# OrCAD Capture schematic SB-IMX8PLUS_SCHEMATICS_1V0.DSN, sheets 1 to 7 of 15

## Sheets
1 01. Block Diagram: title: SB-iMX8PLUS   01. INDEX; rev: 1.0; note: 8000171000
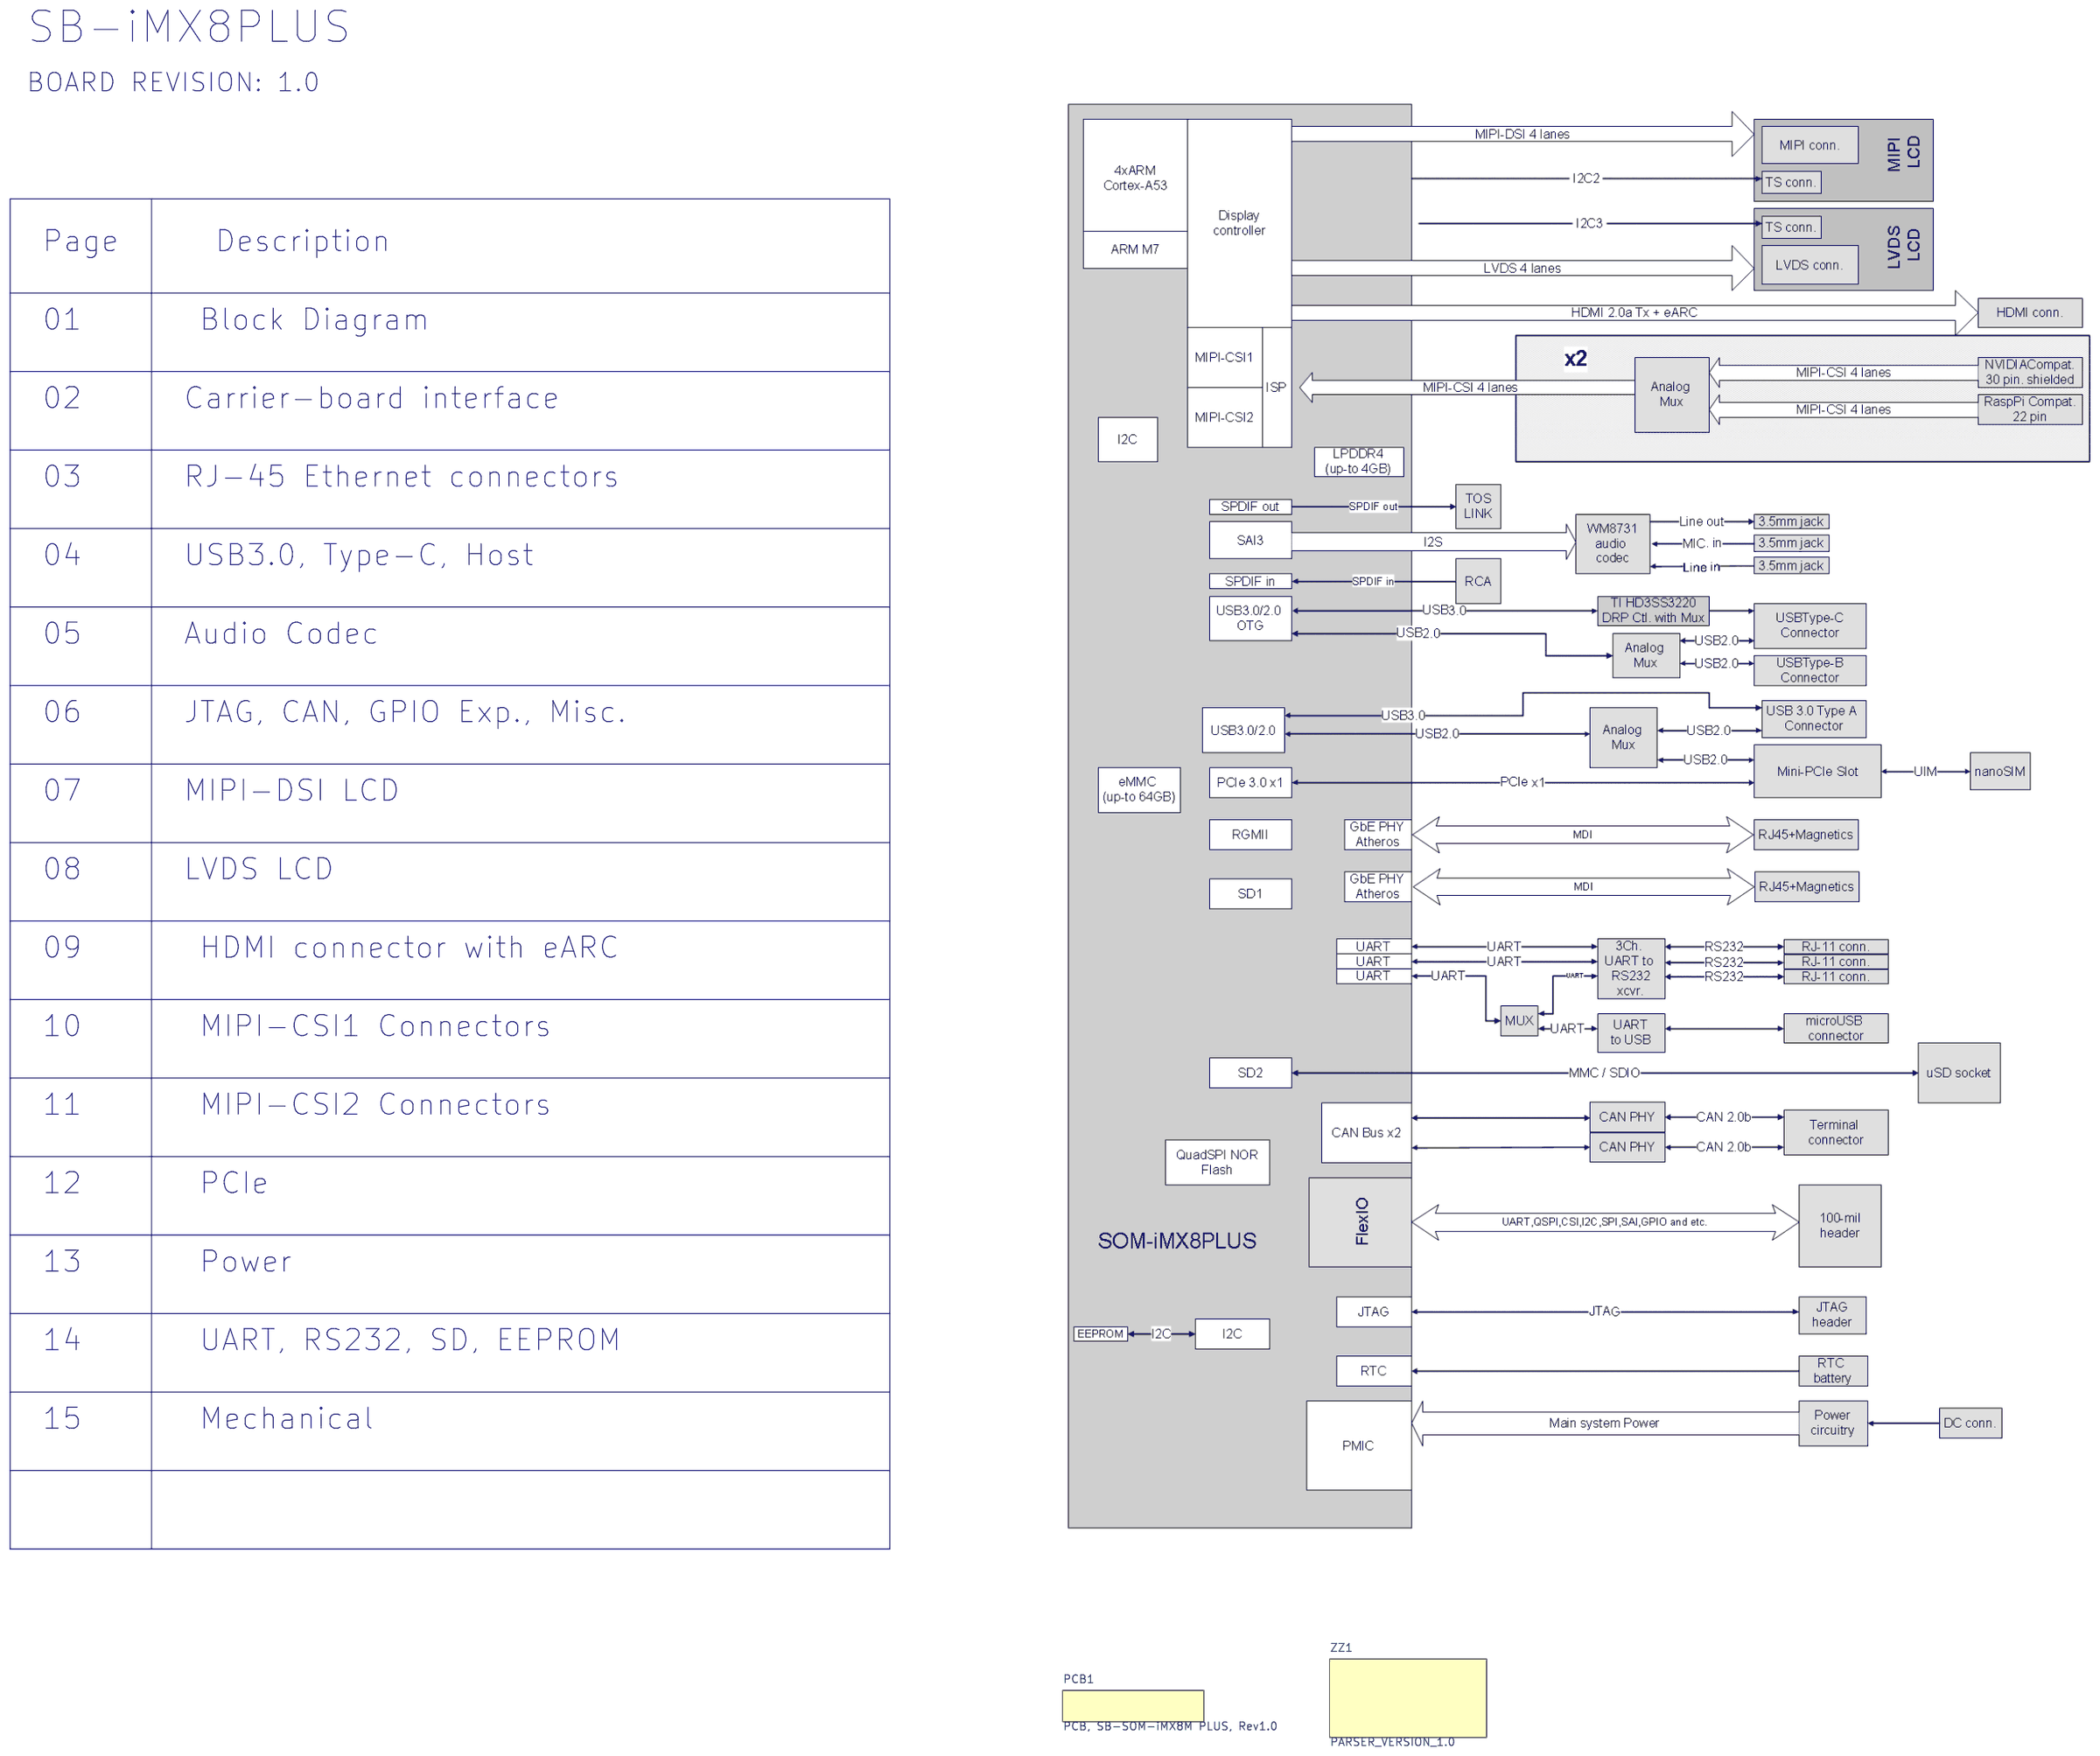
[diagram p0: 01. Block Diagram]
2 02. Carrier Board interface: size C; title: SB-iMX8 PLUS   02. CARRIER BOARD INTERFACE; rev: 1.3; note: 17 HaYetsira Street; note: Yokneam Illit, Israel 2069208
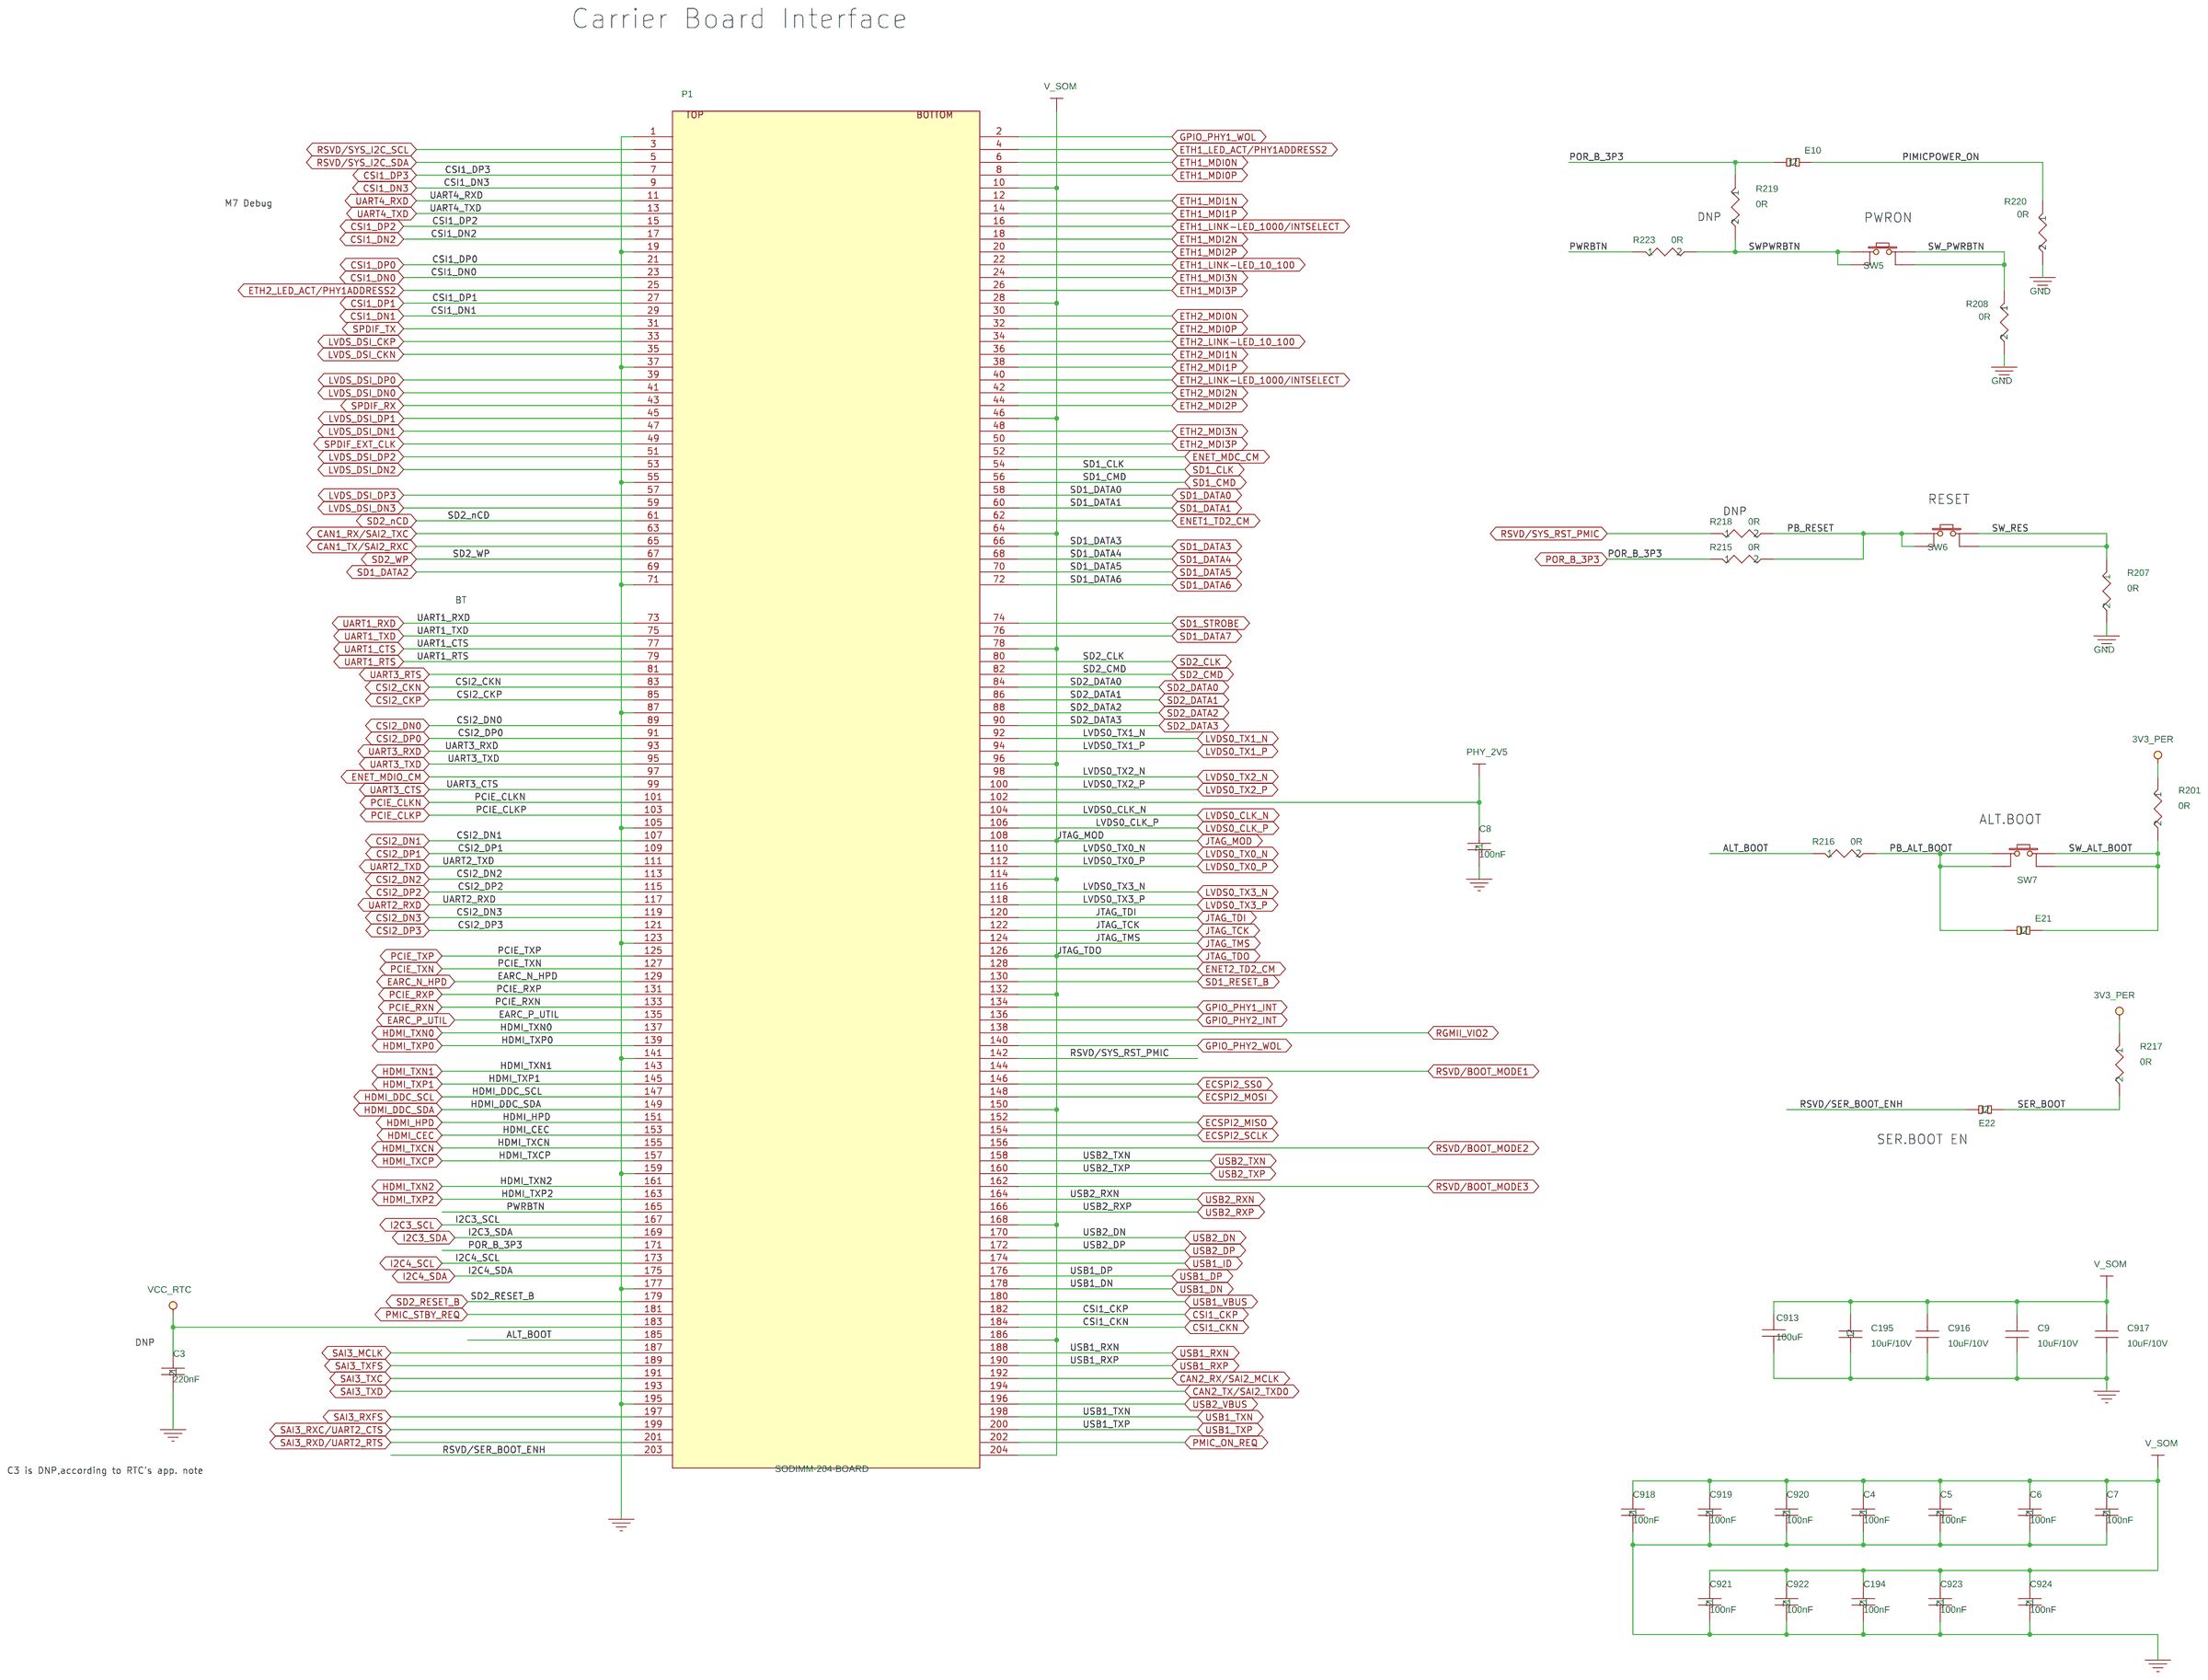
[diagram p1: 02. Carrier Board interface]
3 03. RJ-45 Ethernet connector: size A3; title: SB-iMX8PLUS      03. Gigabit Ethernet
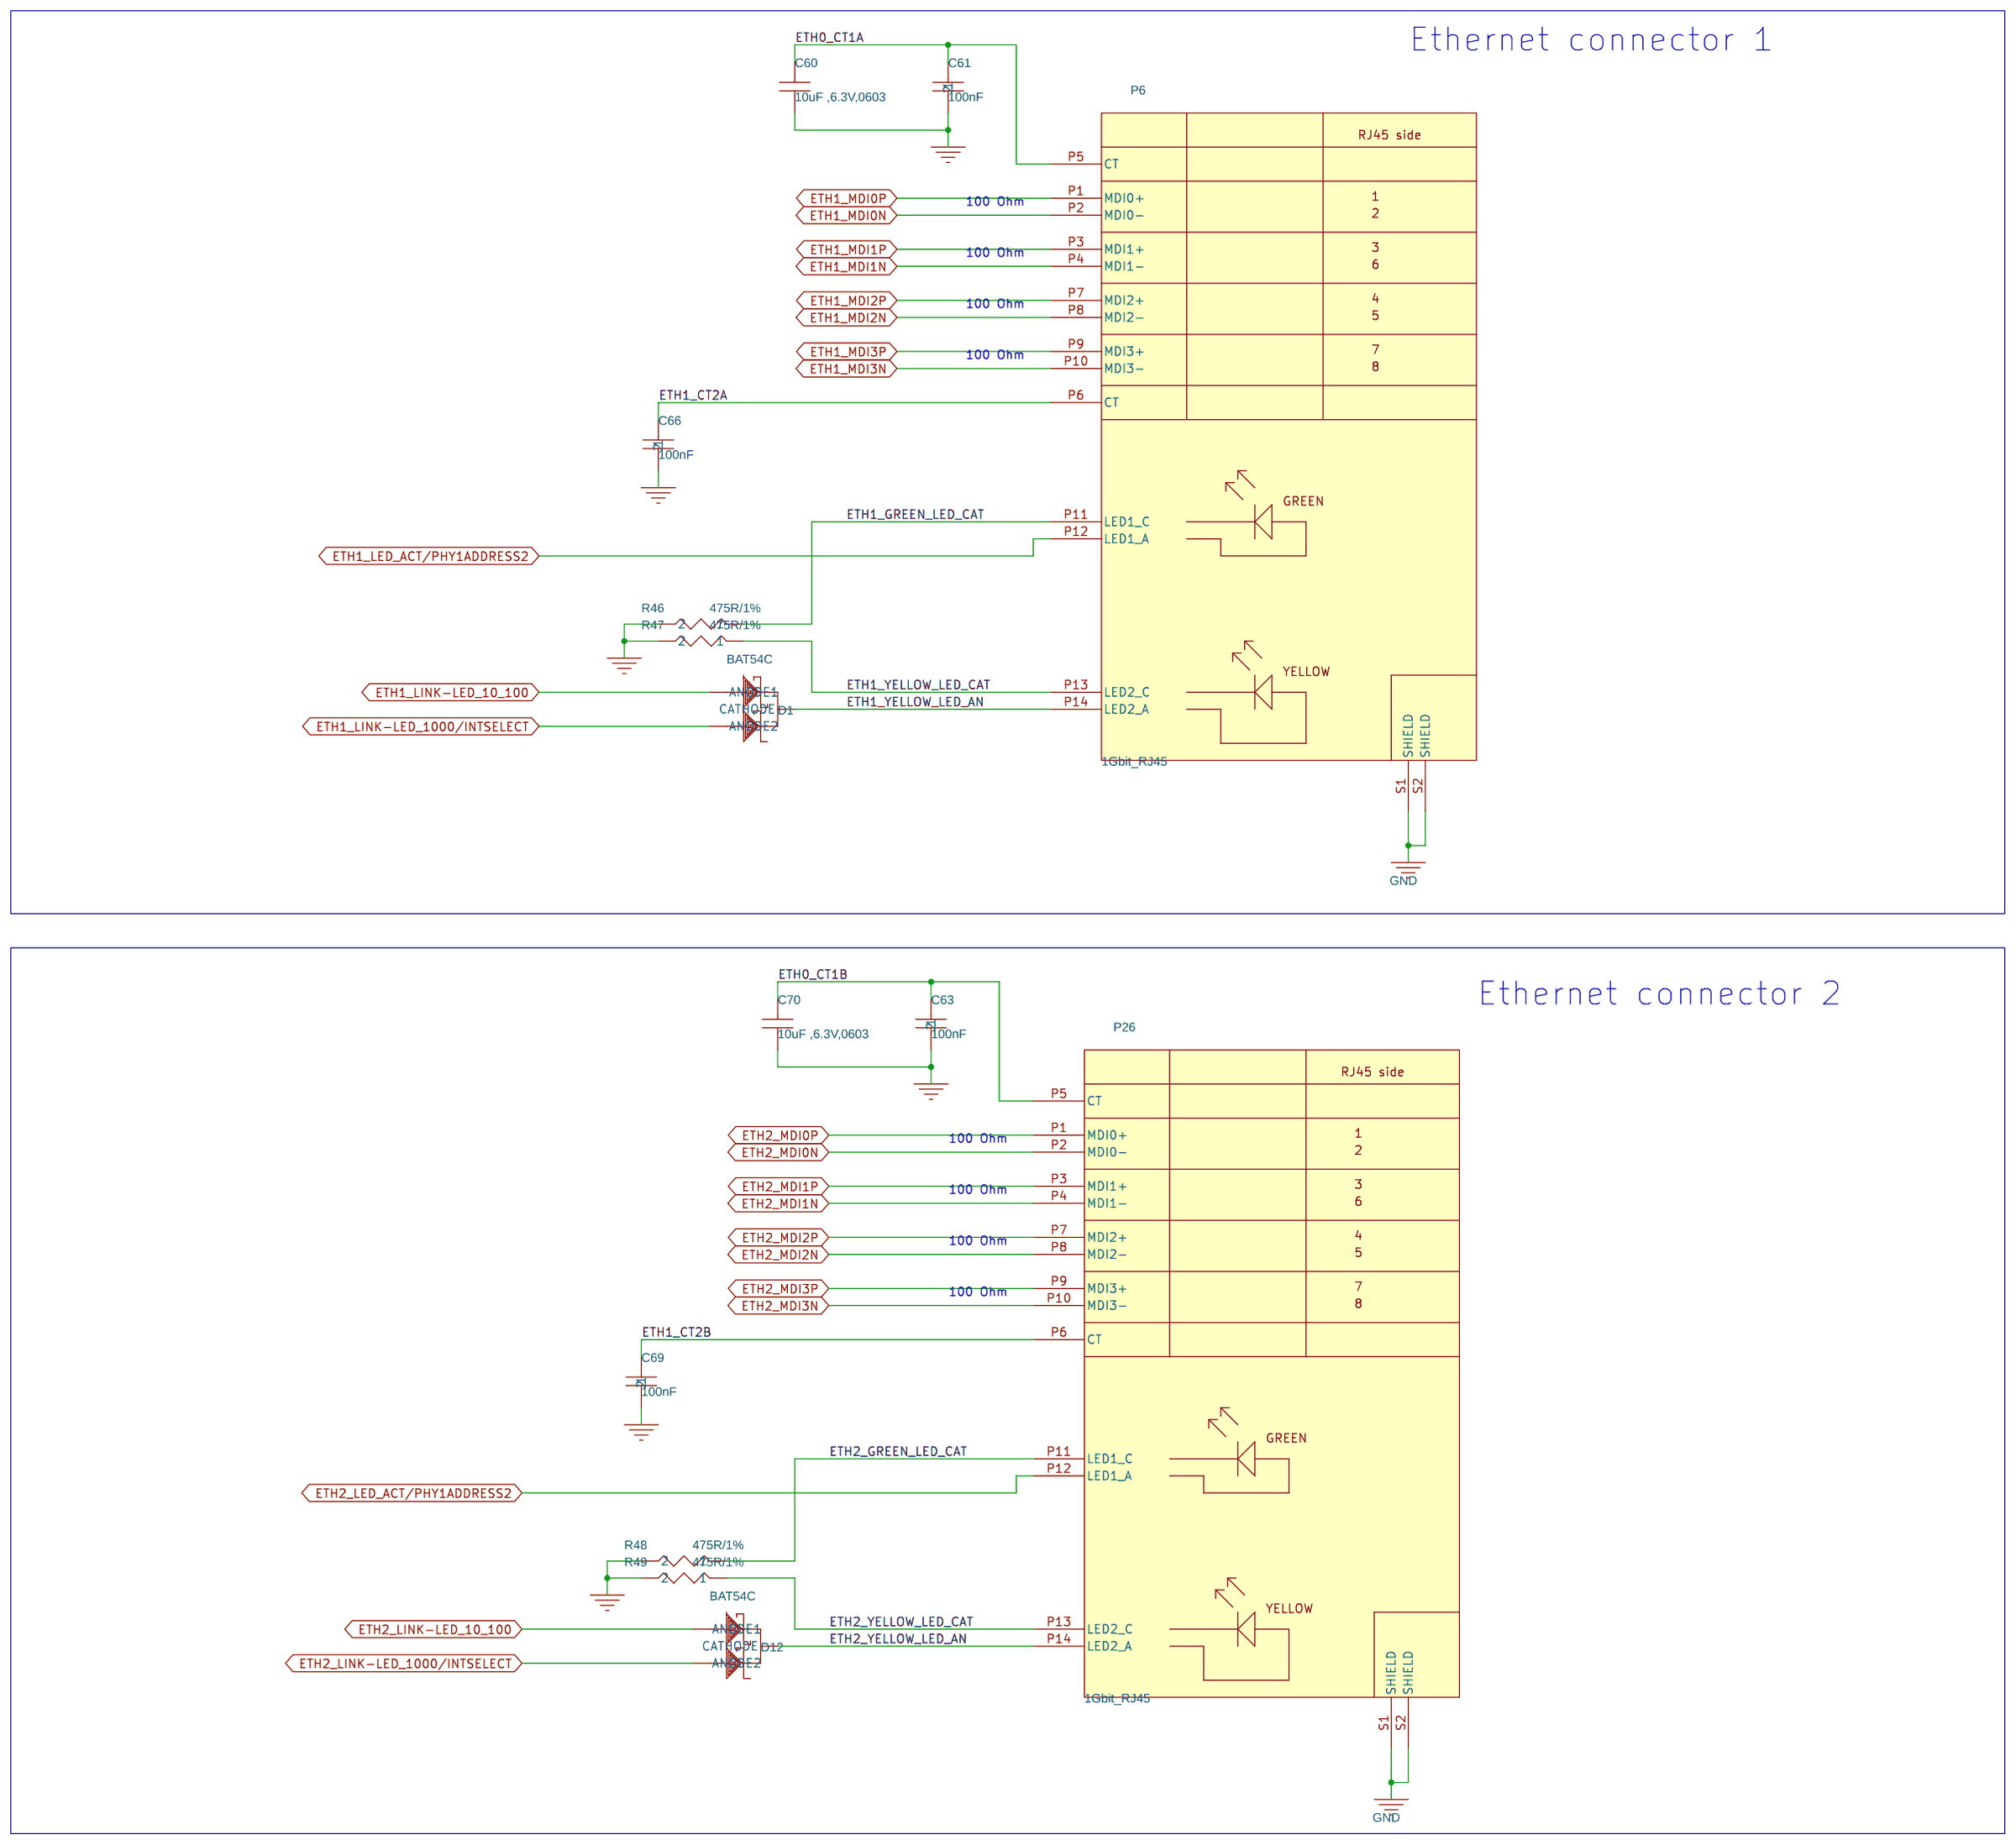
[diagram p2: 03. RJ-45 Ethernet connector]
4 04. USB3.0, Type-C, Host: size A3; title: SB-iMX8PLUS    04. USB3.0, Type-C, Host
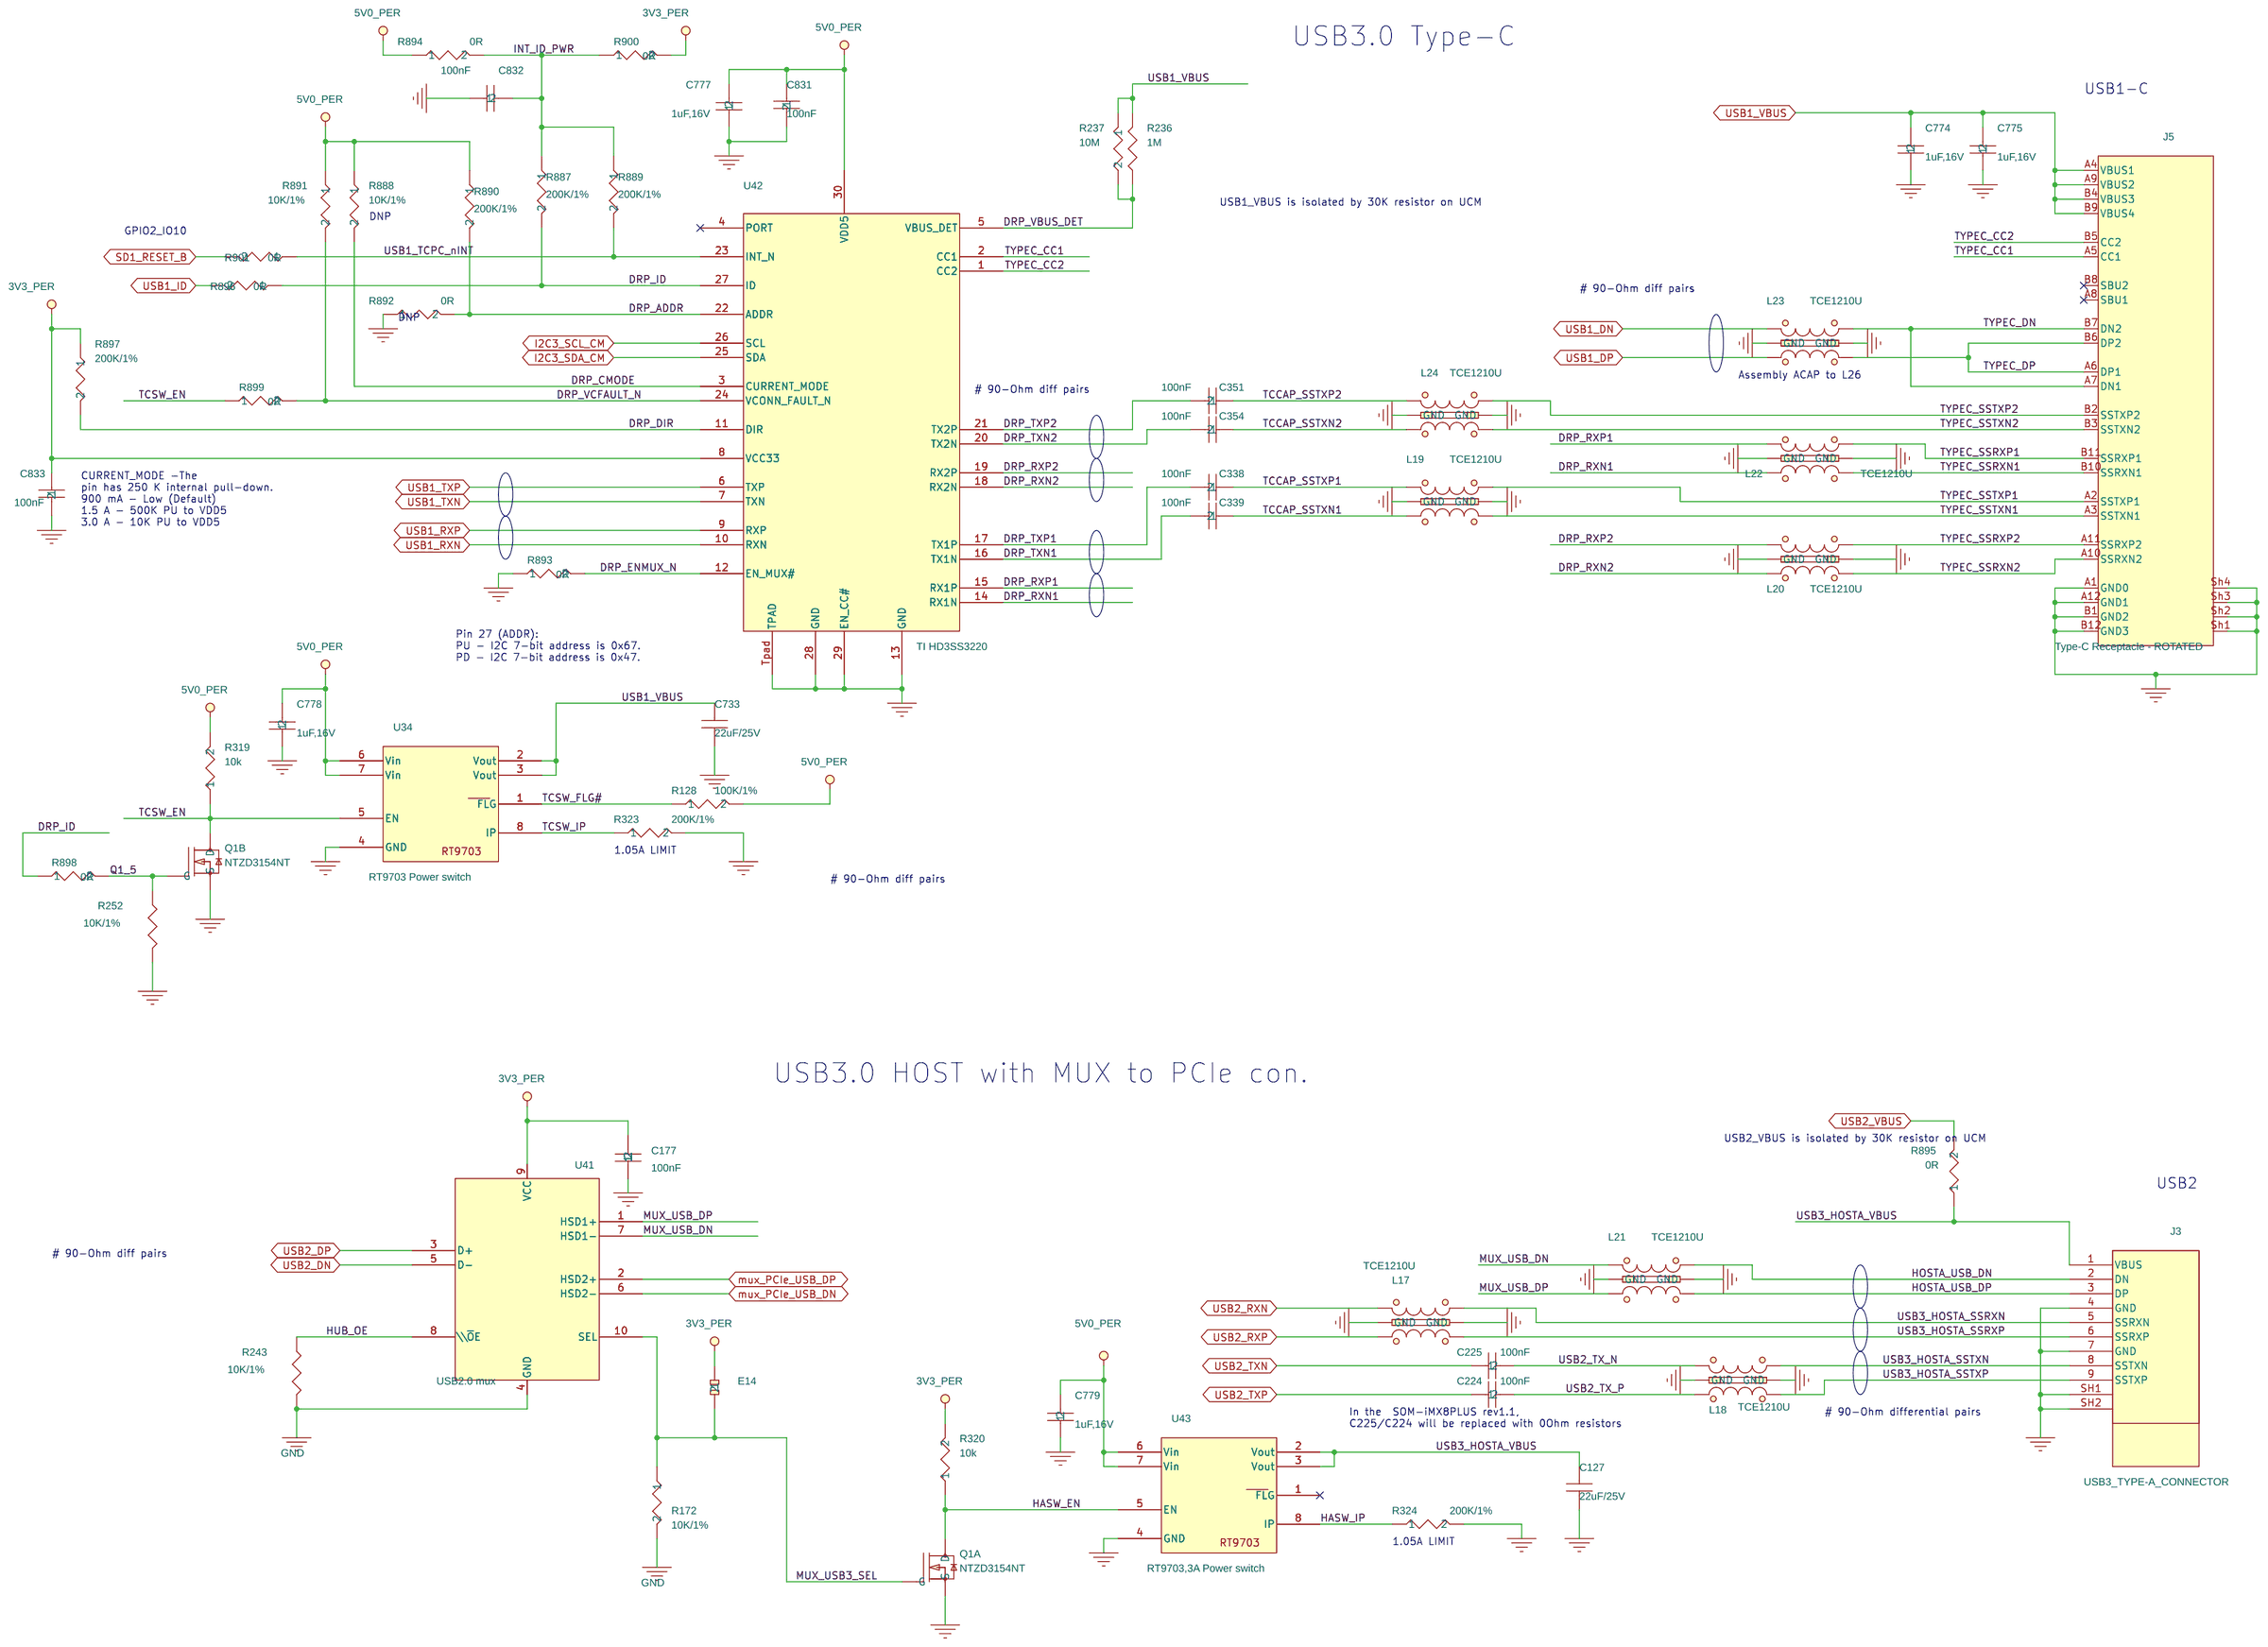
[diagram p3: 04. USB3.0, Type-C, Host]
5 05. Audio Codec: size A3; title: SB-iMX8PLUS      05. AUDIO,SPDIF
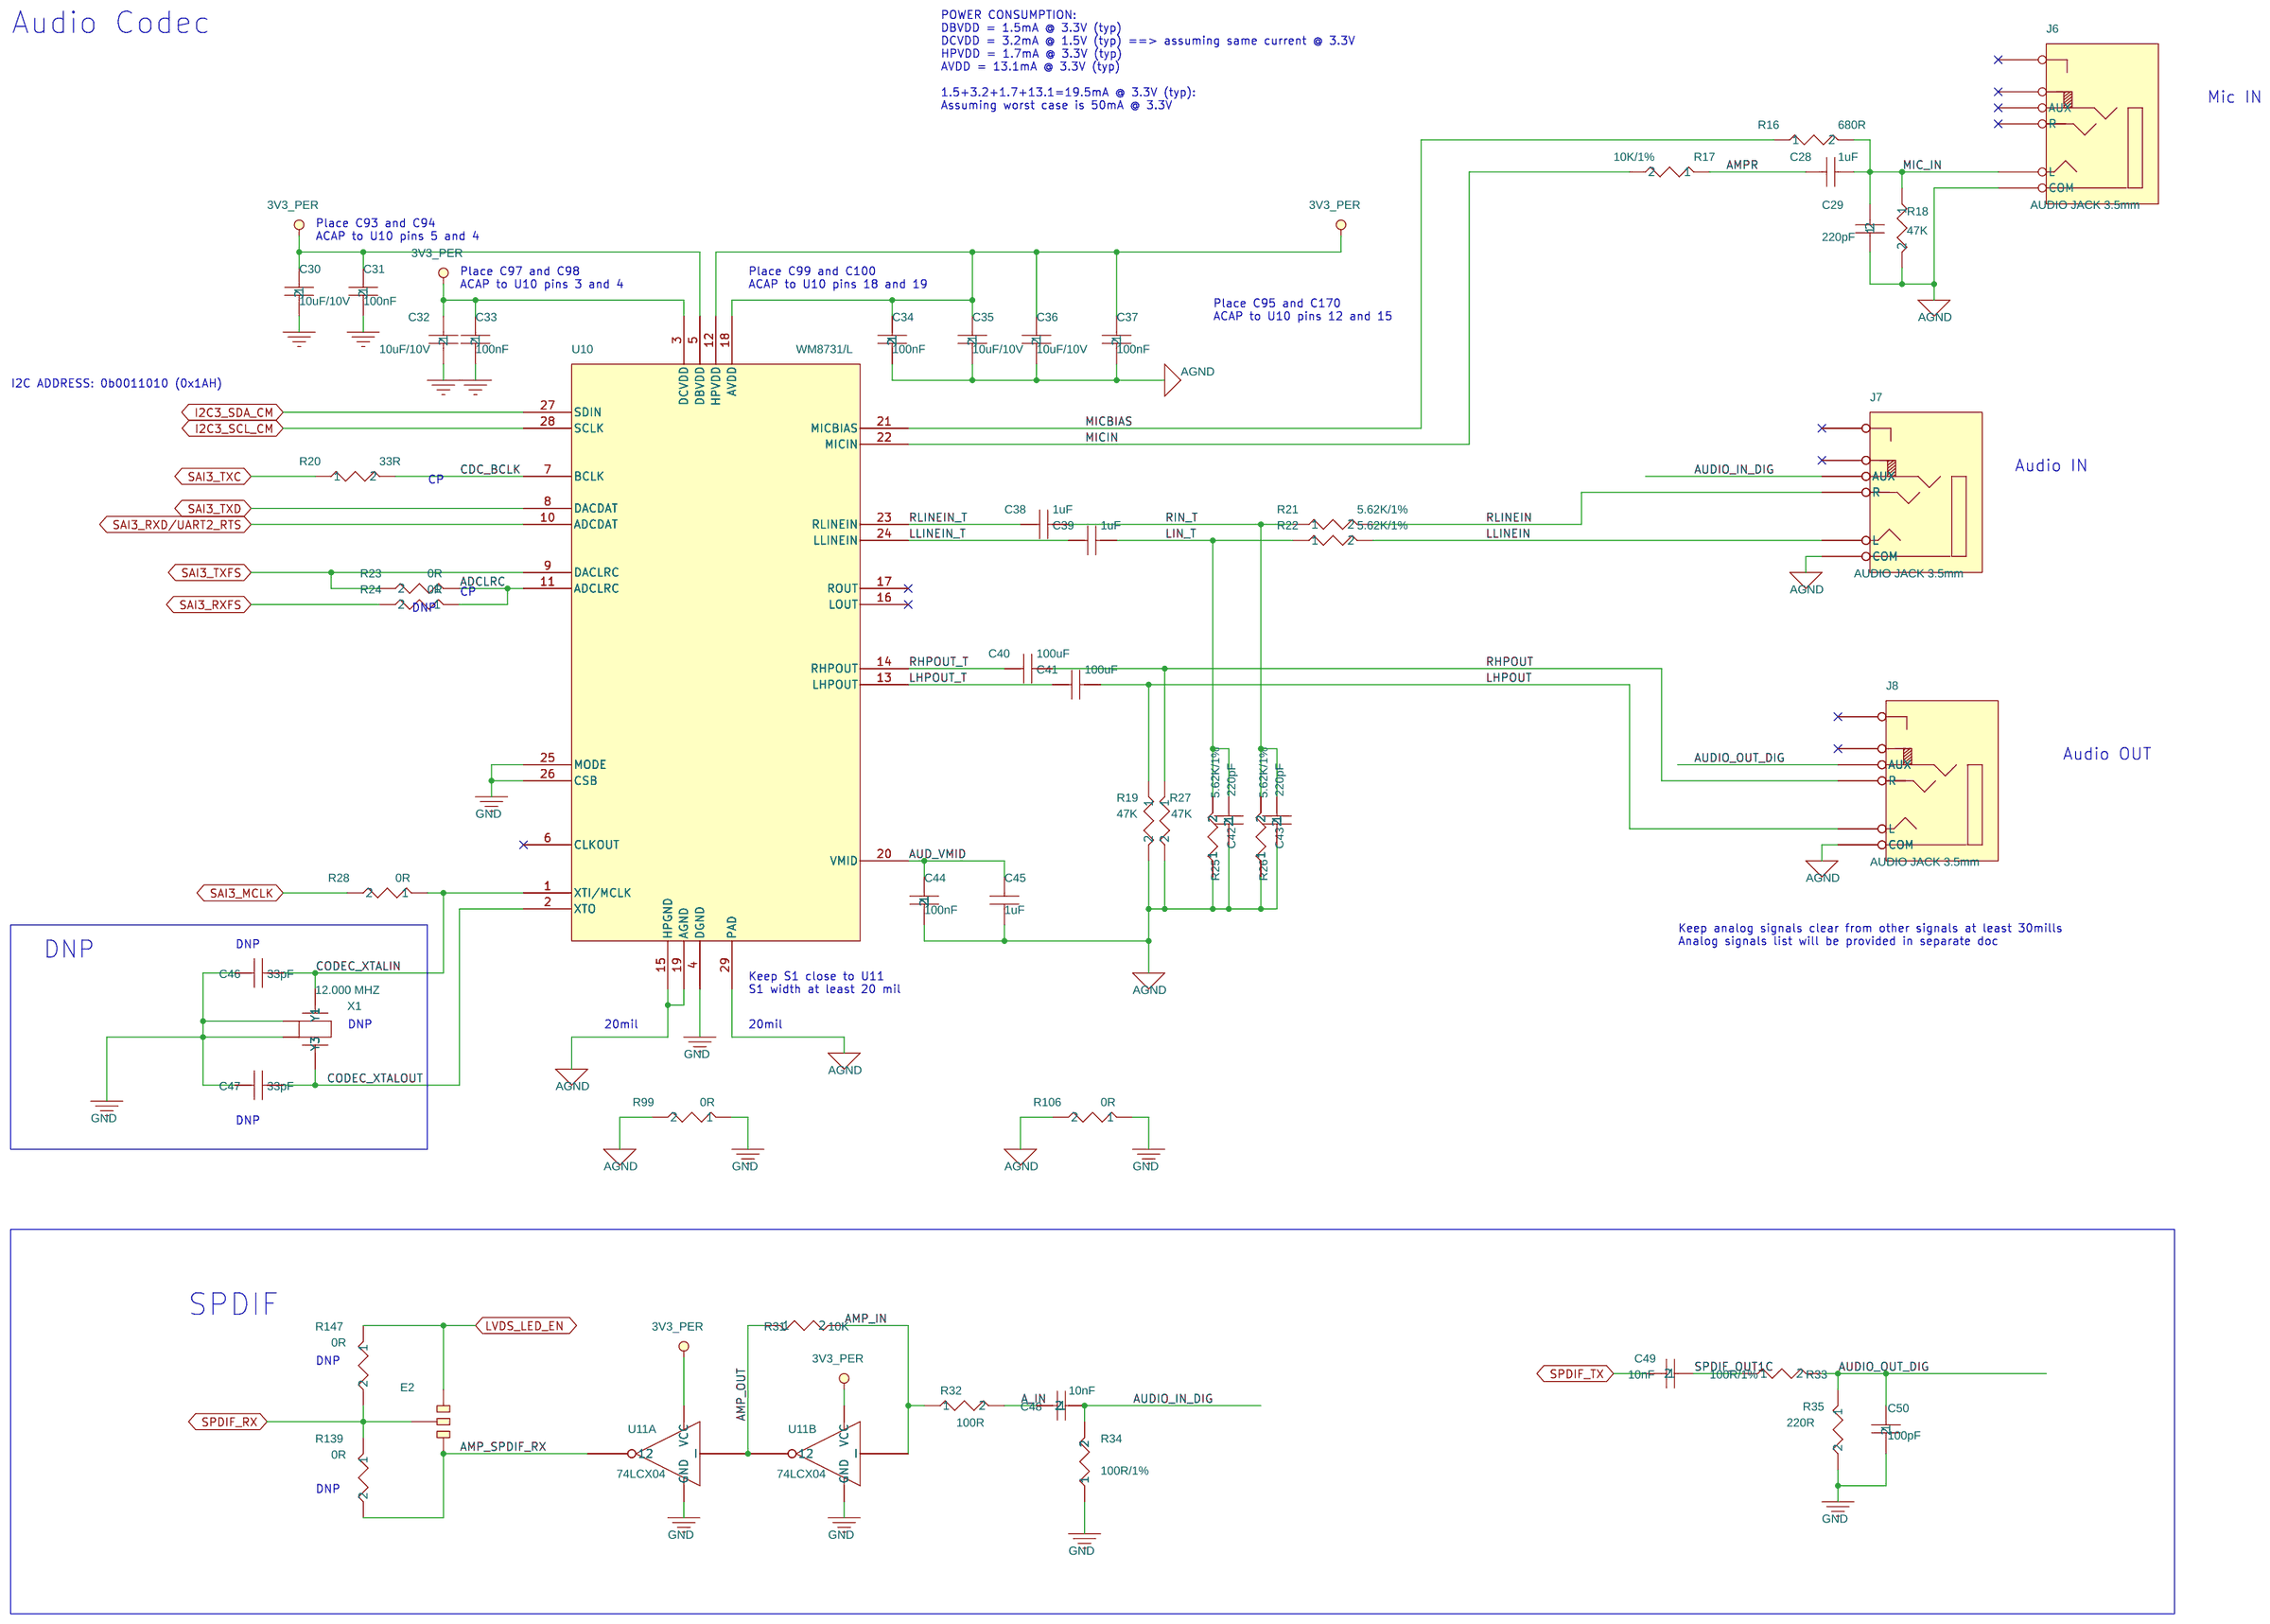
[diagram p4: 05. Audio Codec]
6 06. JTAG, CAN, GPIO Exp., Misc.: size A2; title: SB-iMX8PLUS    06. JTAG, CAN, GPIO Exp., Misc.
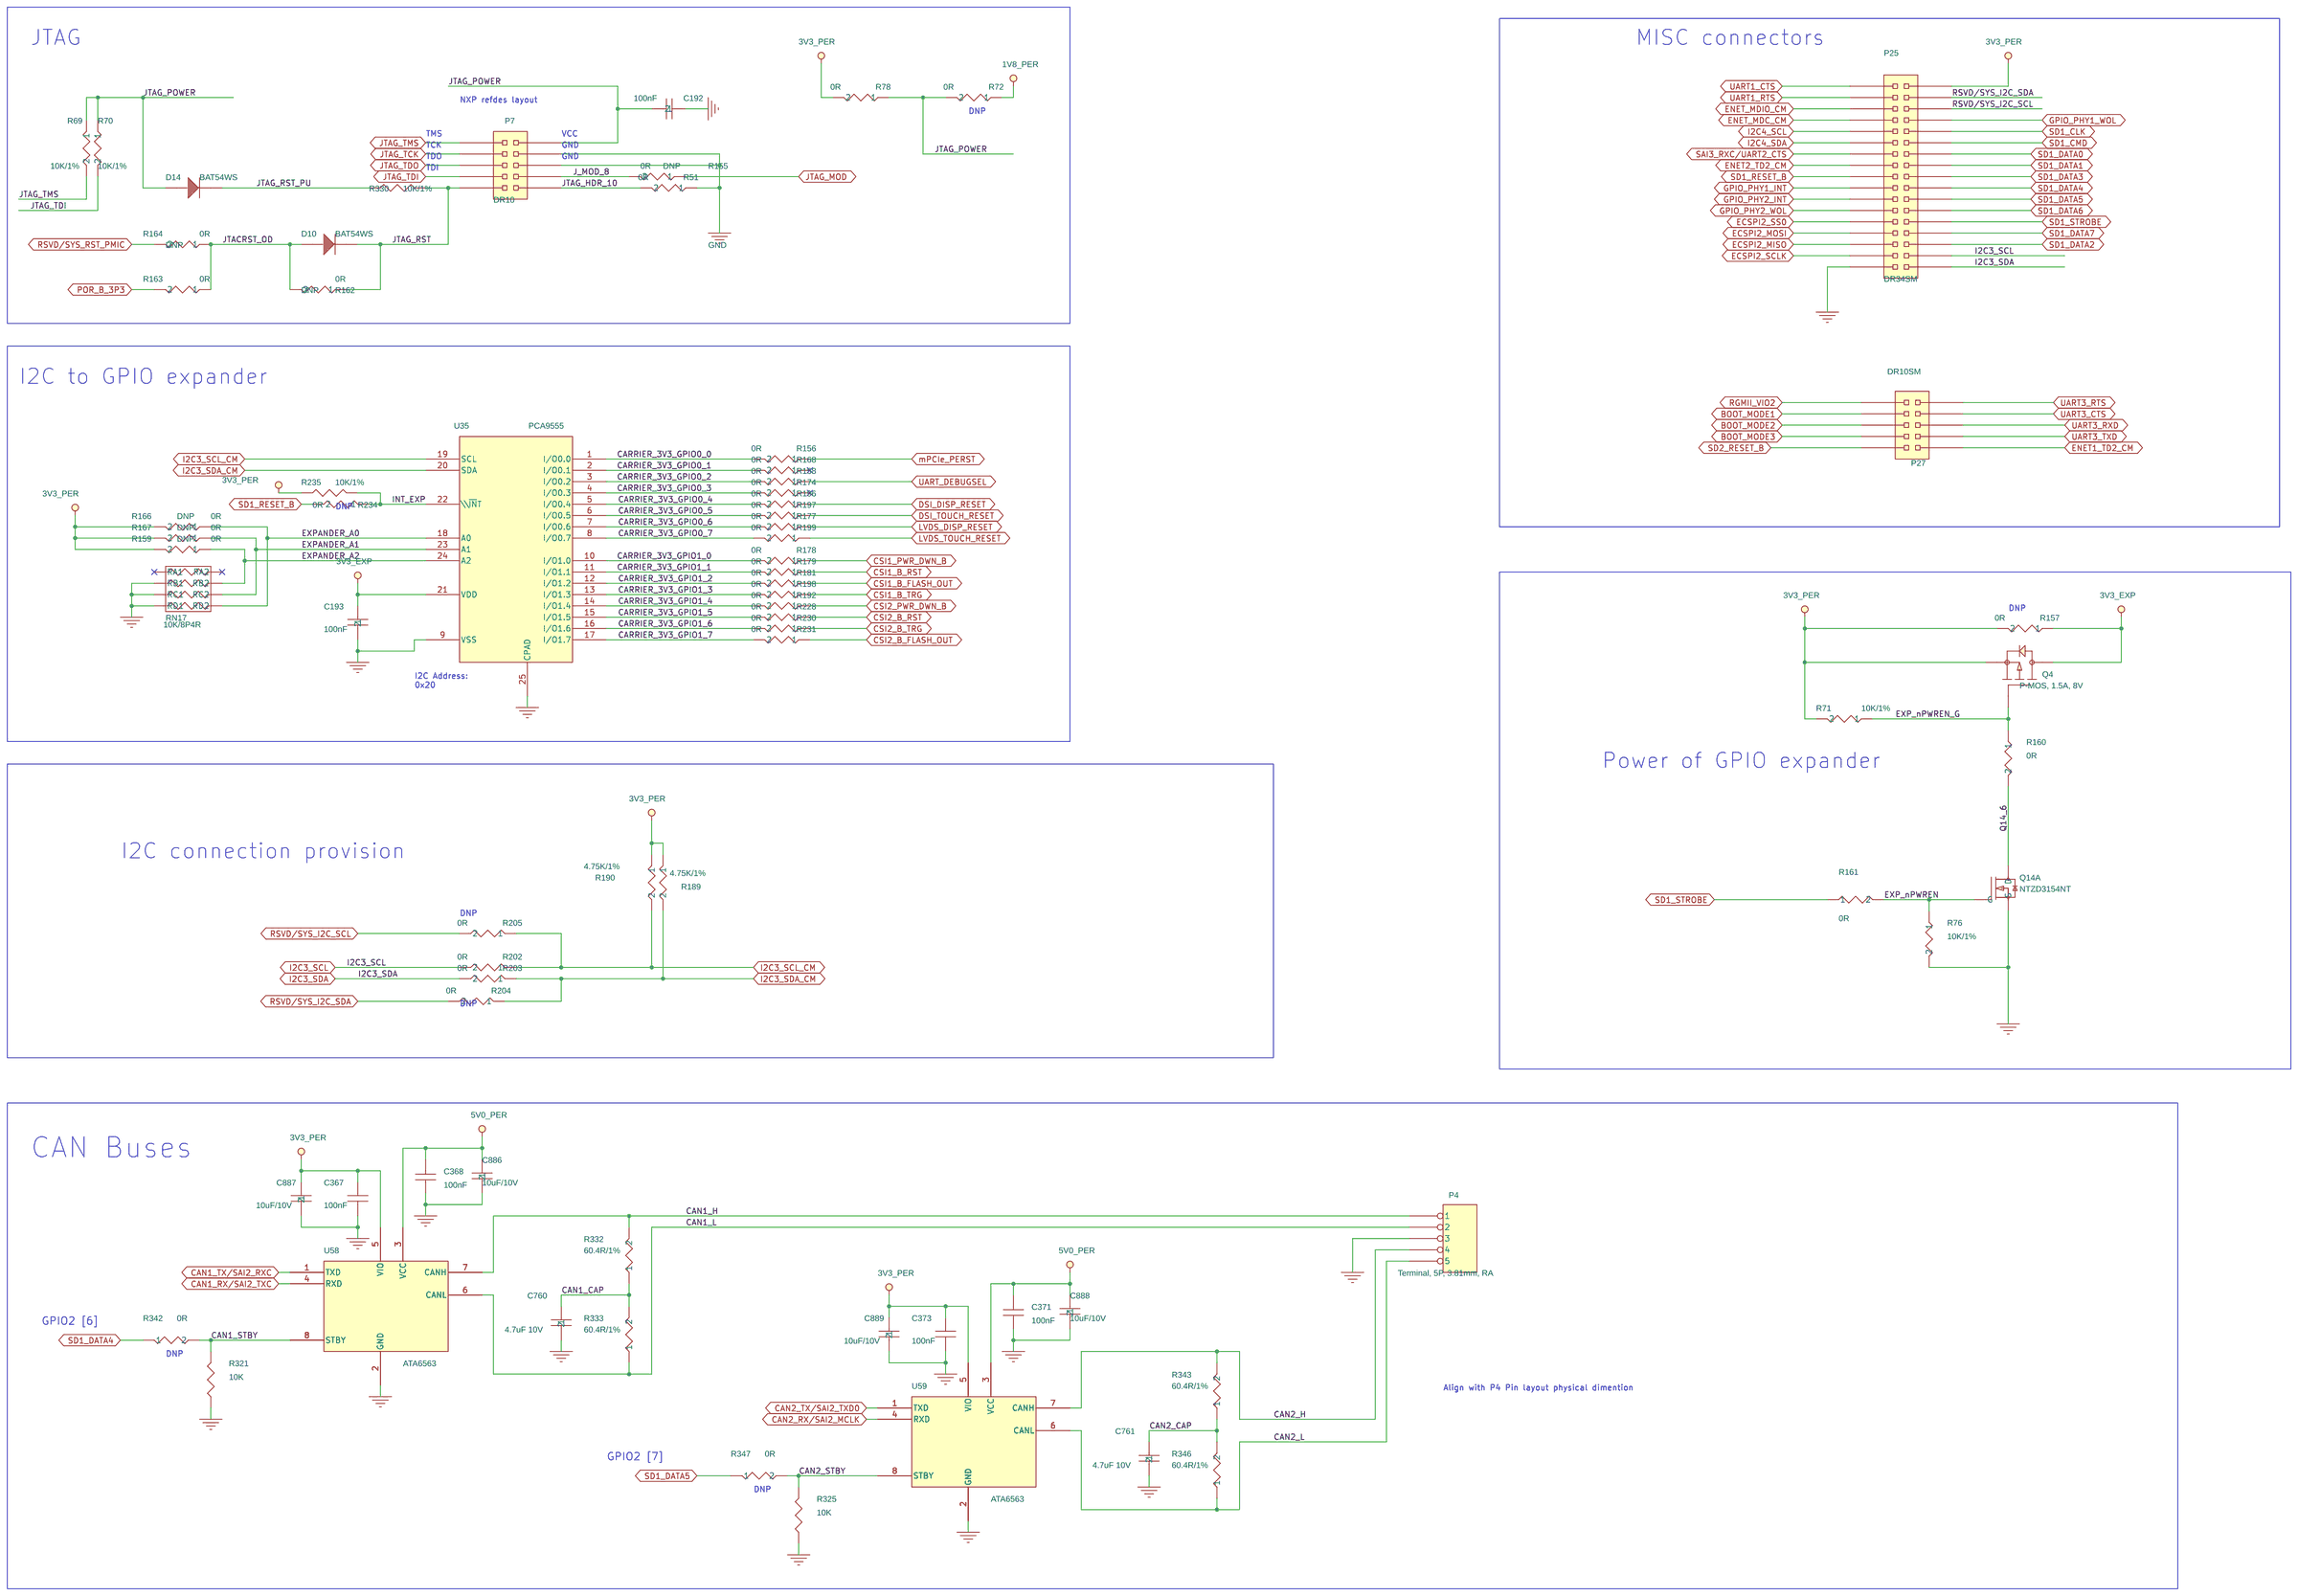
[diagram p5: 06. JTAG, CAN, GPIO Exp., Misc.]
7 07. MIPI-DSI LCD: size A3; title: SB-iMX8PLUS   07. MIPI-DSI LCD
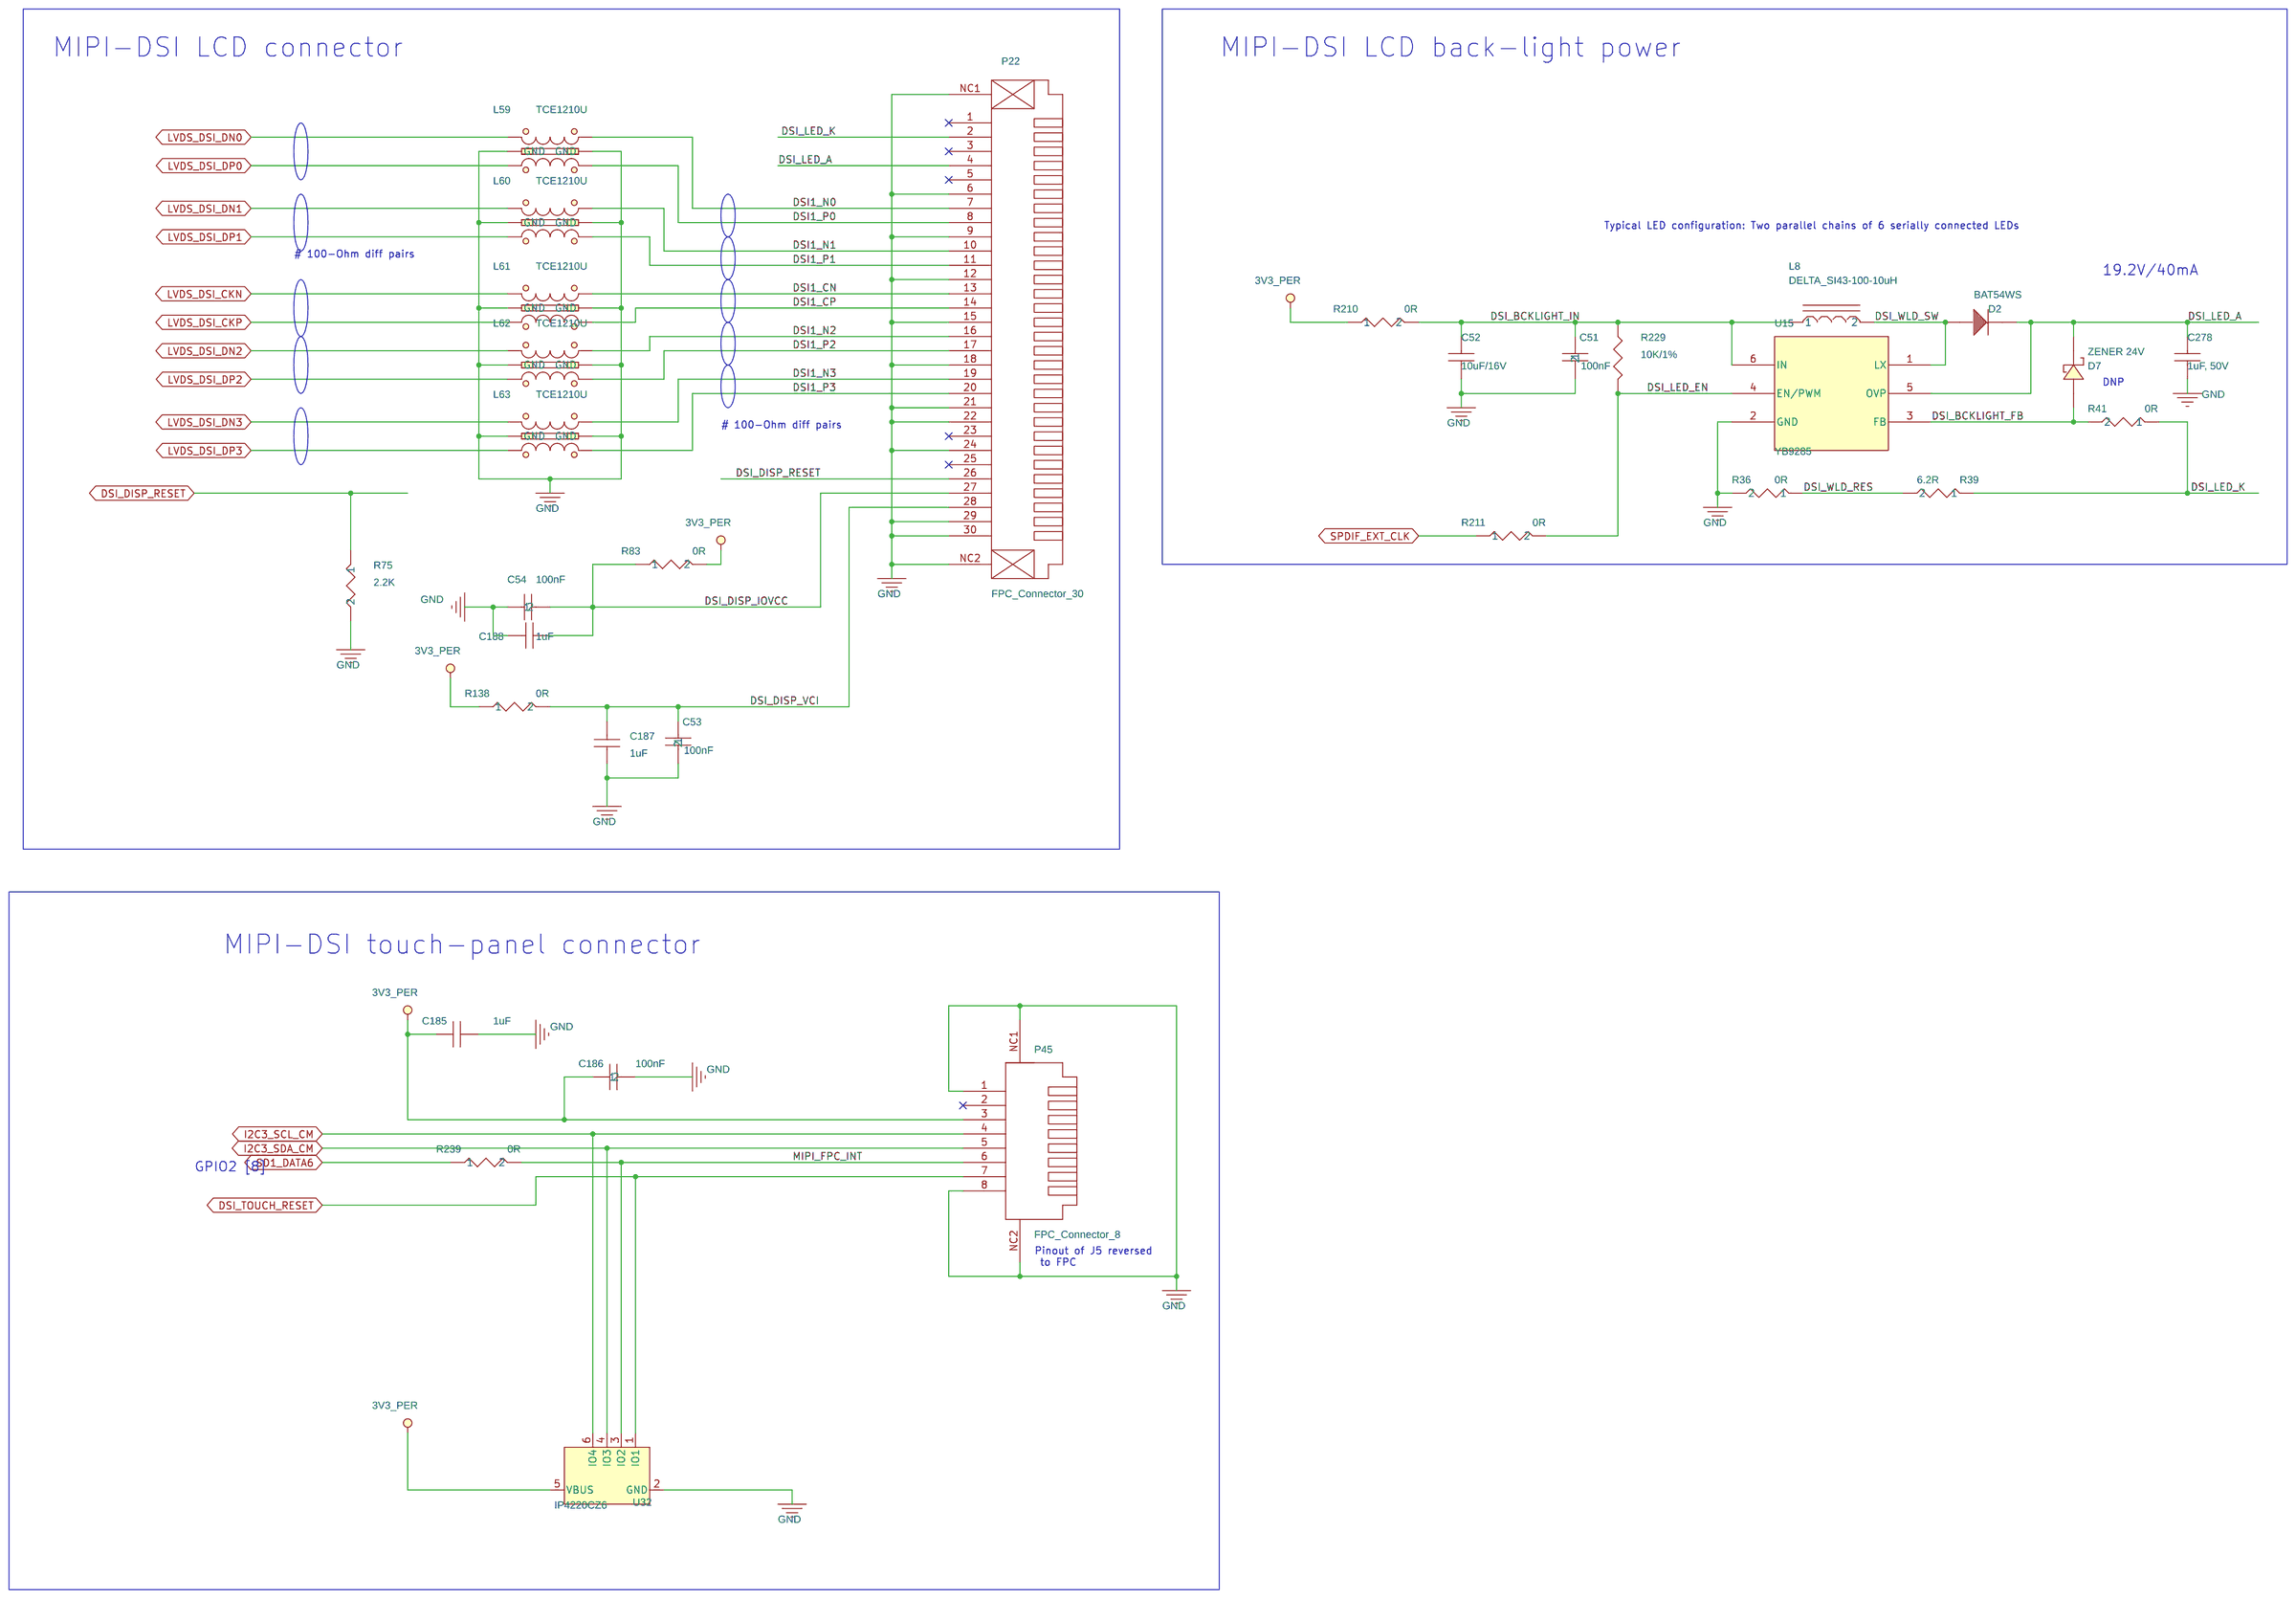
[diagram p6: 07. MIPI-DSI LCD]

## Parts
sheet 01. Block Diagram
PCB1  PCB, SB-SOM-iMX8M PLUS, Rev1.0
ZZ1  PARSER_VERSION_1.0
sheet 02. Carrier Board interface
C3  220nF  [RC0402]
C4  100nF  [RC0402]
C5  100nF  [RC0402]
C6  100nF  [RC0402]
C7  100nF  [RC0402]
C8  100nF  [RC0402]
C9  10uF/10V  [0402]
C194  100nF  [RC0402]
C195  10uF/10V  [0402]
C913  100uF  [C1210H2_5]
C916  10uF/10V  [0402]
C917  10uF/10V  [0402]
C918  100nF  [RC0402]
C919  100nF  [RC0402]
C920  100nF  [RC0402]
C921  100nF  [RC0402]
C922  100nF  [RC0402]
C923  100nF  [RC0402]
C924  100nF  [RC0402]
E10  HDR1X2  [1X2THHDR]
E21  HDR1X2  [1X2THHDR]
E22  HDR1X2  [1X2THHDR]
P1  SODIMM-204-BOARD  [RC0402]
R201  0R  [RC0402]
R207  0R  [RC0402]
R208  0R  [RC0402]
R215  0R  [RC0402]
R216  0R  [RC0402]
R217  0R  [RC0402]
R218  0R  [RC0402]
R219  0R  [RC0402]
R220  0R  [RC0402]
R223  0R  [RC0402]
SW5  PushB  [TACTSW6x6SM]
SW6  PushB  [TACTSW6x6SM]
SW7  PushB  [TACTSW6x6SM]
sheet 03. RJ-45 Ethernet connector
C60  10uF ,6.3V,0603  [RC0603]
C61  100nF  [RC0402]
C63  100nF  [RC0402]
C66  100nF  [RC0402]
C69  100nF  [RC0402]
C70  10uF ,6.3V,0603  [RC0603]
D1  BAT54C  [SOT23]
D12  BAT54C  [SOT23]
P6  1Gbit_RJ45  [DUSBRJ-1G]
P26  1Gbit_RJ45  [DUSBRJ-1G]
R46  475R/1%  [RC0402]
R47  475R/1%  [RC0402]
R48  475R/1%  [RC0402]
R49  475R/1%  [RC0402]
sheet 04. USB3.0, Type-C, Host
C127  22uF/25V  [C0805]
C177  100nF  [RC0402]
C224  100nF  [RC0402]
C225  100nF  [RC0402]
C338  100nF  [RC0402]
C339  100nF  [RC0402]
C351  100nF  [RC0402]
C354  100nF  [RC0402]
C733  22uF/25V  [C0805]
C774  1uF,16V  [RC0402]
C775  1uF,16V  [RC0402]
C777  1uF,16V  [RC0402]
C778  1uF,16V  [RC0402]
C779  1uF,16V  [RC0402]
C831  100nF  [RC0402]
C832  100nF  [RC0402]
C833  100nF  [RC0402]
E14  HDR1X2  [1X2THHDR]
J3  USB3_TYPE-A_CONNECTOR  [USB3_TYPEA]
J5  Type-C Receptacle - ROTATED  [USB3_1-C-SM]
L17  TCE1210U  [EMI1012-ESD]
L18  TCE1210U  [EMI1012-ESD]
L19  TCE1210U  [EMI1012-ESD]
L20  TCE1210U  [EMI1012-ESD]
L21  TCE1210U  [EMI1012-ESD]
L22  TCE1210U  [EMI1012-ESD]
L23  TCE1210U  [EMI1012-ESD]
L24  TCE1210U  [EMI1012-ESD]
Q1  NTZD3154NT  [SOT-563-6]  (sections A,B)
R128  100K/1%  [RC0402]
R172  10K/1%  [RC0402]
R236  1M  [RC0402]
R237  10M  [RC0402]
R243  10K/1%  [RC0402]
R252  10K/1%  [RC0402]
R319  10k  [RC0402]
R320  10k  [RC0402]
R323  200K/1%  [RC0402]
R324  200K/1%  [RC0402]
R887  200K/1%  [RC0402]
R888  10K/1%  [RC0402]
R889  200K/1%  [RC0402]
R890  200K/1%  [RC0402]
R891  10K/1%  [RC0402]
R892  0R  [RC0402]
R893  0R  [RC0402]
R894  0R  [RC0402]
R895  0R  [RC0402]
R896  0R  [RC0402]
R897  200K/1%  [RC0402]
R898  0R  [RC0402]
R899  0R  [RC0402]
R900  0R  [RC0402]
R901  0R  [RC0402]
U34  RT9703 Power switch  [SO8-150]
U41  USB2.0 mux  [MO-255U1418E]
U42  TI HD3SS3220  [QFN2_6x4_6-30]
U43  RT9703,3A Power switch  [SO8-150]
sheet 05. Audio Codec
C28  1uF  [RC0402]
C29  220pF  [RC0603]
C30  10uF/10V  [RC0402]
C31  100nF  [RC0402]
C32  10uF/10V  [RC0402]
C33  100nF  [RC0402]
C34  100nF  [RC0402]
C35  10uF/10V  [RC0402]
C36  10uF/10V  [RC0402]
C37  100nF  [RC0402]
C38  1uF  [RC0402]
C39  1uF  [RC0402]
C40  100uF  [C1206]
C41  100uF  [C1206]
C42  220pF  [RC0603]
C43  220pF  [RC0603]
C44  100nF  [RC0402]
C45  1uF  [RC0402]
C46  33pF  [RC0402]
C47  33pF  [RC0402]
C48  10nF  [RC0402]
C49  10nF  [RC0402]
C50  100pF  [RC0402]
E2  JP3  [1X3THHDR]
J6  AUDIO JACK 3.5mm  [AJ35-4P-SW-SM]
J7  AUDIO JACK 3.5mm  [AJ35-4P-SW-SM]
J8  AUDIO JACK 3.5mm  [AJ35-4P-SW-SM]
R16  680R  [RC0402]
R17  10K/1%  [RC0402]
R18  47K  [RC0402]
R19  47K  [RC0402]
R20  33R  [RC0402]
R21  5.62K/1%  [RC0402]
R22  5.62K/1%  [RC0402]
R23  0R  [RC0402]
R24  0R  [RC0402]
R25  5.62K/1%  [RC0402]
R26  5.62K/1%  [RC0402]
R27  47K  [RC0402]
R28  0R  [RC0402]
R31  10K  [RC0402]
R32  100R  [RC0402]
R33  100R/1%  [RC0402]
R34  100R/1%  [RC0402]
R35  220R  [RC0402]
R99  0R  [RC0402]
R106  0R  [RC0402]
R139  0R  [RC0402]
R147  0R  [RC0402]
U10  WM8731/L  [MO-220VHHD-1]
X1  12.000 MHZ  [OSC3225]
sheet 06. JTAG, CAN, GPIO Exp., Misc.
C192  100nF  [RC0402]
C193  100nF  [RC0402]
C367  100nF  [RC0402]
C368  100nF  [RC0402]
C371  100nF  [RC0402]
C373  100nF  [RC0402]
C760  4.7uF 10V  [RC0402]
C761  4.7uF 10V  [RC0402]
C886  10uF/10V  [RC0402]
C887  10uF/10V  [RC0402]
C888  10uF/10V  [RC0402]
C889  10uF/10V  [RC0402]
D10  BAT54WS  [SOD-323]
D14  BAT54WS  [SOD-323]
P4  Terminal, 5P, 3.81mm, RA  [TB3.81mmRA-5P]
P7  DR10  [2X5THHDR]
P25  DR34SM  [2X17SMHDR]
P27  DR10SM  [2X5SMHDR]
Q4  P-MOS, 1.5A, 8V  [SOT23]
Q14  NTZD3154NT  [SOT-563-6]  (sections A,B)
R51  0R  [RC0402]
R69  10K/1%  [RC0402]
R70  10K/1%  [RC0402]
R71  10K/1%  [RC0402]
R72  0R  [RC0402]
R76  10K/1%  [RC0402]
R78  0R  [RC0402]
R155  0R  [RC0402]
R156  0R  [RC0402]
R157  0R  [RC0402]
R158  0R  [RC0402]
R159  0R  [RC0402]
R160  0R  [RC0402]
R161  0R  [RC0402]
R162  0R  [RC0402]
R163  0R  [RC0402]
R164  0R  [RC0402]
R166  0R  [RC0402]
R167  0R  [RC0402]
R168  0R  [RC0402]
R174  0R  [RC0402]
R177  0R  [RC0402]
R178  0R  [RC0402]
R179  0R  [RC0402]
R181  0R  [RC0402]
R189  4.75K/1%  [RC0402]
R190  4.75K/1%  [RC0402]
R192  0R  [RC0402]
R196  0R  [RC0402]
R197  0R  [RC0402]
R198  0R  [RC0402]
R199  0R  [RC0402]
R202  0R  [RC0402]
R203  0R  [RC0402]
R204  0R  [RC0402]
R205  0R  [RC0402]
R228  0R  [RC0402]
R230  0R  [RC0402]
R231  0R  [RC0402]
R234  0R  [RC0402]
R235  10K/1%  [RC0402]
R321  10K  [RC0402]
R325  10K  [RC0402]
R330  10K/1%  [RC0402]
R332  60.4R/1%  [RC0402]
R333  60.4R/1%  [RC0402]
R342  0R  [RC0402]
R343  60.4R/1%  [RC0402]
R346  60.4R/1%  [RC0402]
R347  0R  [RC0402]
RN17  10K/8P4R  [RESNET8P0805]
U35  PCA9555  [QFN4x4-24]
U58  ATA6563  [SOI8-150]
U59  ATA6563  [SOI8-150]
sheet 07. MIPI-DSI LCD
C51  100nF  [RC0402]
C52  10uF/16V  [RC0603]
C53  100nF  [RC0402]
C54  100nF  [RC0402]
C185  1uF  [RC0402]
C186  100nF  [RC0402]
C187  1uF  [RC0402]
C188  1uF  [RC0402]
C278  1uF, 50V  [RC0603]
D2  BAT54WS  [SOD-323]
D7  ZENER 24V  [SOD-123]
L8  DELTA_SI43-100-10uH  [IND4x4x2_5]
L59  TCE1210U  [EMI1012-ESD]
L60  TCE1210U  [EMI1012-ESD]
L61  TCE1210U  [EMI1012-ESD]
L62  TCE1210U  [EMI1012-ESD]
L63  TCE1210U  [EMI1012-ESD]
P22  FPC_Connector_30  [FPC_30]
P45  FPC_Connector_8  [FPC_8]
R36  0R  [RC0402]
R39  6.2R  [RC0402]
R41  0R  [RC0402]
R75  2.2K  [RC0402]
R83  0R  [RC0402]
R138  0R  [RC0402]
R210  0R  [RC0402]
R211  0R  [RC0402]
R229  10K/1%  [RC0402]
R239  0R  [RC0402]
U15  YB9285  [SOT23-6L]
U32  IP4220CZ6  [SOT23-6L]
sheet 14. UART, RS232, SD, EEPROM
U11  74LCX04  [TSSOP-14]  (sections A,B,F)

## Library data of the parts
PCB1 = PCB,_EM-X270_Rev_1_0.1: CLABCONF0: = SB-iMX8PLUS; P/N: 188C03910
ZZ1 = PARSER_VERSION_1_1.0: CLABCONF0: DNP
C3 = 100nF,_10V,_X7R,_10%,_0402_4: CLABCONF0: DNP; P/N: 151C22400S
C4 C34 C54 C66 C193 = 100nF,_10V,_X7R,_10%,_0402_1: CLABCONF0: = SB-iMX8PLUS
C5 = 100nF,_10V,_X7R,_10%,_0402_6: CLABCONF0: = SB-iMX8PLUS
C6 C33 C53 C69 C192 C351 = 100nF,_10V,_X7R,_10%,_0402: CLABCONF0: = SB-iMX8PLUS
C7 C339 = 100nF,_10V,_X7R,_10%,_0402_12: CLABCONF0: = SB-iMX8PLUS
C8 C37 C63 C186 = 100nF,_10V,_X7R,_10%,_0402_2: CLABCONF0: = SB-iMX8PLUS
C9 = 10uF,6.3V,0603,20%X5R_1: CLABCONF0: = SB-iMX8PLUS; P/N: 151B10600S
C194 C354 = 100nF,_10V,_X7R,_10%,_0402_9: CLABCONF0: = SB-iMX8PLUS
C30 C195 C888 = 10uF_10V_20%_0402: CLABCONF0: = SB-iMX8PLUS
C913 = 100uF,_6.3V,_X5R,_20%,_1206: CLABCONF0: = SB-iMX8PLUS
C916 = 10uF,6.3V,0603,20%X5R_2: CLABCONF0: = SB-iMX8PLUS; P/N: 151B10600S
C917 = 10uF,6.3V,0603,20%X5R: CLABCONF0: = SB-iMX8PLUS; P/N: 151B10600S
C44 C51 C61 C338 C918 = 100nF,_10V,_X7R,_10%,_0402_3: CLABCONF0: = SB-iMX8PLUS
C919 = 100nF,_10V,_X7R,_10%,_0402_5: CLABCONF0: = SB-iMX8PLUS
C920 = 100nF,_10V,_X7R,_10%,_0402_10: CLABCONF0: = SB-iMX8PLUS
C921 = 100nF,_10V,_X7R,_10%,_0402_8: CLABCONF0: = SB-iMX8PLUS
C922 = 100nF,_10V,_X7R,_10%,_0402_13: CLABCONF0: = SB-iMX8PLUS
C923 = 100nF,_10V,_X7R,_10%,_0402_11: CLABCONF0: = SB-iMX8PLUS
C832 C924 = 100nF,_10V,_X7R,_10%,_0402_7: CLABCONF0: = SB-iMX8PLUS
E10 = HDR_1x2_100MIL_TH_JUMPER_2: CLABCONF0: = SB-iMX8PLUS
E21 = HDR_1x2_100MIL_TH_JUMPER_1: CLABCONF0: = SB-iMX8PLUS
E14 E22 = HDR_1x2_100MIL_TH_JUMPER: CLABCONF0: = SB-iMX8PLUS
P1 = SODIMM-204_2: CLABCONF0: = SB-iMX8PLUS; P/N: 190I20400S
R201 = 0R,_0402_0_2: CLABCONF0: = SB-iMX8PLUS; P/N: 161C00005S
R207 = 0R,_0402_0_8: CLABCONF0: = SB-iMX8PLUS; P/N: 161C00005S
R203 R208 = 0R,_0402_0_4: CLABCONF0: = SB-iMX8PLUS; P/N: 161C00005S
R215 = 0R,_0402_0_1: CLABCONF0: = SB-iMX8PLUS; P/N: 161C00005S
R202 R216 = 0R,_0402_0: CLABCONF0: = SB-iMX8PLUS; P/N: 161C00005S
R217 = 0R,_0402_0_7: CLABCONF0: = SB-iMX8PLUS; P/N: 161C00005S
R204 R218 = 0R,_0402_0_3: CLABCONF0: DNP; P/N: 161C00005S
R219 = 0R,_0402_0_9: CLABCONF0: DNP; P/N: 161C00005S
R220 = 0R,_0402_0_6: CLABCONF0: = SB-iMX8PLUS; P/N: 161C00005S
R223 = 0R,_0402_0_5: CLABCONF0: = SB-iMX8PLUS; P/N: 161C00005S
SW5-SW7 = TACT_SW_6x6mm_SMT: CLABCONF0: = SB-iMX8PLUS
C60 = Cap.,10uF,6.3V,0603,X5R_1: CLABCONF0: = SB-iMX8PLUS
C70 = Cap.,10uF,6.3V,0603,X5R: CLABCONF0: = SB-iMX8PLUS
D1 D12 = BAT54C: CLABCONF0: = SB-iMX8PLUS
P6 P26 = Con_0.,1GBit_RJ45,_short: CLABCONF0: = SB-iMX8PLUS
R46 = 475R_1%,_0402_3: CLABCONF0: = SB-iMX8PLUS
R47 = 475R_1%,_0402_2: CLABCONF0: = SB-iMX8PLUS
R48 = 475R_1%,_0402: CLABCONF0: = SB-iMX8PLUS
R49 = 475R_1%,_0402_1: CLABCONF0: = SB-iMX8PLUS
C127 = 22uF,25V,_0805_1: CLABCONF0: = SB-iMX8PLUS
C177 = 100nF,_10V,_X7R,_10%,_0402_2: CLABCONF0: = SB-iMX8PLUS; Group: LAN2
C224 = 100nF,_10V,_X7R,_10%,_0402_6: CLABCONF0: =SOM-iMX8PLUS
C225 = 100nF,_10V,_X7R,_10%,_0402_11: CLABCONF0: =SOM-iMX8PLUS
C733 = 22uF,25V,_0805: CLABCONF0: = SB-iMX8PLUS
C774 = 100nF,_10V,_X7R,_10%,_0402_13: CLABCONF0: = SB-iMX8PLUS; P/N: 151C10500S
C775 = 100nF,_10V,_X7R,_10%,_0402_1: CLABCONF0: = SB-iMX8PLUS; P/N: 151C10500S
C777 = 100nF,_10V,_X7R,_10%,_0402_10: CLABCONF0: = SB-iMX8PLUS; P/N: 151C10500S
C778 = 100nF,_10V,_X7R,_10%,_0402_8: CLABCONF0: = SB-iMX8PLUS; P/N: 151C10500S
C779 = 100nF,_10V,_X7R,_10%,_0402_5: CLABCONF0: = SB-iMX8PLUS; P/N: 151C10500S
C831 = 100nF,_10V,_X7R,_10%,_0402_14: CLABCONF0: = SB-iMX8PLUS
C31 C833 = 100nF,_10V,_X7R,_10%,_0402_4: CLABCONF0: = SB-iMX8PLUS
J3 = USB3_TYPEA_CONNECTER_0: CLABCONF0: = SB-iMX8PLUS
J5 = USBTypeC_Receptacle_TOPMount_2: CLABCONF0: = SB-iMX8PLUS; P/N: 180K02401S
L17-L24 L59-L63 = ESD_CHOKE_DIFFx2_10: CLABCONF0: = SB-iMX8PLUS; P/N: 142D11801S
Q1 Q14 = N-MOSFET_Dual: CLABCONF0: = SB-iMX8PLUS; P/N: 131D31540S
R128 = 100K,_1%,_0402,_1_16W_1: CLABCONF0: = SB-iMX8PLUS
R69 R172 = 10K,1%,0402,1_16W_2: CLABCONF0: = SB-iMX8PLUS
R236 = RESISTOR: CLABCONF0: = SB-iMX8PLUS; P/N: 161C10045S
R237 = 10M,5%,0402,1_16W: CLABCONF0: = SB-iMX8PLUS
R243 R321 = 10K,1%,0402,1_16W_0_1: CLABCONF0: = SB-iMX8PLUS
R229 R252 = 10K,1%,0402,1_16W_0: CLABCONF0: = SB-iMX8PLUS
R319 = 1M_,5%,_0402: CLABCONF0: = SB-iMX8PLUS; P/N: 161C10021S
R320 = 1M_,5%,_0402_1: CLABCONF0: = SB-iMX8PLUS; P/N: 161C10021S
R323 = 100K,_1%,_0402,_1_16W_3: CLABCONF0: = SB-iMX8PLUS; P/N: 161C20031S
R324 = 100K,_1%,_0402,_1_16W_5: CLABCONF0: = SB-iMX8PLUS; P/N: 161C20031S
R887 = 100K,_1%,_0402,_1_16W_4: CLABCONF0: = SB-iMX8PLUS; P/N: 161C20031S
R888 = 10K,1%,0402,1_16W_1: CLABCONF0: DNP
R889 = 100K,_1%,_0402,_1_16W_6: CLABCONF0: = SB-iMX8PLUS; P/N: 161C20031S
R890 = 100K,_1%,_0402,_1_16W: CLABCONF0: = SB-iMX8PLUS; P/N: 161C20031S
R31 R76 R891 = 10K,1%,0402,1_16W: CLABCONF0: = SB-iMX8PLUS
R892 = 0R,_0402_6: CLABCONF0: DNP
R83 R893 = 0R,_0402_2: CLABCONF0: = SB-iMX8PLUS
R894 = 0R,_0402_4: CLABCONF0: DNP
R895 = 0R,_0402: CLABCONF0: DNP
R896 = 0R,_0402_8: CLABCONF0: DNP
R897 = 100K,_1%,_0402,_1_16W_2: CLABCONF0: = SB-iMX8PLUS; P/N: 161C20031S
R72 R898 = 0R,_0402_1: CLABCONF0: DNP
R899 = 0R,_0402_7: CLABCONF0: DNP
R211 R900 = 0R,_0402_3: CLABCONF0: DNP
R901 = 0R,_0402_5: CLABCONF0: DNP
U34 U43 = RT9703,3A_Power_switch+FLG: CLABCONF0: = SB-iMX8PLUS
U41 = USB2_0.0_mux: CLABCONF0: = SB-iMX8PLUS; P/N: 116A72220S
U42 = TI_HD3SS3220: CLABCONF0: = SB-iMX8PLUS
C28 C38 C39 C45 C185 C187 C188 = 1uF,X5R,6.3V,0402: CLABCONF0: = SB-iMX8PLUS
C29 = 220pF,50V,NPO,0603_2: CLABCONF0: = SB-iMX8PLUS
C32 C886 = 10uF_10V_20%_0402_1: CLABCONF0: = SB-iMX8PLUS
C35 C887 = 10uF_10V_20%_0402_2: CLABCONF0: = SB-iMX8PLUS
C36 C889 = 10uF_10V_20%_0402_3: CLABCONF0: = SB-iMX8PLUS
C40 C41 = 100uF,_6.3V,_X5R,_20%,_1210: CLABCONF0: = SB-iMX8PLUS; P/N: 151B10730S
C42 = 220pF,50V,NPO,0603_1: CLABCONF0: = SB-iMX8PLUS
C43 = 220pF,50V,NPO,0603: CLABCONF0: = SB-iMX8PLUS
C46 C47 = 33pF,50V,NPO,10%,0402_0: CLABCONF0: DNP
C48 = 10nF,_25V,_X7R,_10%,_0402_1: CLABCONF0: = SB-iMX8PLUS
C49 = 10nF,_25V,_X7R,_10%,_0402: CLABCONF0: = SB-iMX8PLUS
C50 = 100pF,_50V,_NPO,_5%,_0402: CLABCONF0: = SB-iMX8PLUS
E2 = HDR_1x3_100MIL_TH_JUMPER: CLABCONF0: = SB-iMX8PLUS
J6-J8 = Audio_JACK,_STEREO+AUX+SW_3.5mm: CLABCONF0: = SB-iMX8PLUS
R16 = 47K,_0402_1: CLABCONF0: = SB-iMX8PLUS; P/N: 161C68001S
R17 R70 = 10K,1%,0402,1_16W_1: CLABCONF0: = SB-iMX8PLUS
R18 = 47K,_0402: CLABCONF0: = SB-iMX8PLUS
R19 = 47K,_0402_2: CLABCONF0: = SB-iMX8PLUS
R20 = 33R,5%,0402,1_16W_0: CLABCONF0: = SB-iMX8PLUS
R21 = 5.62K_1%,0402_3: CLABCONF0: = SB-iMX8PLUS
R22 = 5.62K_1%,0402_1: CLABCONF0: = SB-iMX8PLUS
R23 = 0R,_0402_0_6: CLABCONF0: = SB-iMX8PLUS
R24 = 0R,_0402_0_4: CLABCONF0: DNP
R25 = 5.62K_1%,0402: CLABCONF0: = SB-iMX8PLUS
R26 = 5.62K_1%,0402_2: CLABCONF0: = SB-iMX8PLUS
R27 = 47K,_0402_3: CLABCONF0: = SB-iMX8PLUS
R28 = 0R,_0402_0_5: CLABCONF0: = SB-iMX8PLUS
R32 = 100R,1%,0402,1_16W_1: CLABCONF0: = SB-iMX8PLUS
R33 = 100R,1%,0402,1_16W_2: CLABCONF0: = SB-iMX8PLUS
R34 = 100R,1%,0402,1_16W: CLABCONF0: = SB-iMX8PLUS
R35 = 220R,5%,0402,1_16W: CLABCONF0: = SB-iMX8PLUS
R99 = 0R,_0402_0_1: CLABCONF0: = SB-iMX8PLUS
R106 = 0R,_0402_0: CLABCONF0: = SB-iMX8PLUS
R139 = 0R,_0402_0_3: CLABCONF0: DNP
R147 = 0R,_0402_0_2: CLABCONF0: DNP
U10 = TSC2046_2: CLABCONF0: = SB-iMX8PLUS; P/N: 117A10010S
X1 = TMP_0: CLABCONF0: DNP; P/N: 141B12604I
C367 C368 C371 C373 = 100nF,_10V,_X7R,_10%,_0402_0: CLABCONF0: = SB-iMX8PLUS
C760 = 4.7uF_0402_10V_20%_1: CLABCONF0: = SB-iMX8PLUS
C761 = 4.7uF_0402_10V_20%: CLABCONF0: = SB-iMX8PLUS
D2 D10 D14 = BAT54WS_0: CLABCONF0: = SB-iMX8PLUS
P4 = Terminal,_5P,_3.81mm,_RA: CLABCONF0: = SB-iMX8PLUS
P7 = HDR_2x5_100MIL_TH: CLABCONF0: = SB-iMX8PLUS
P25 = HDR_2x17_100MIL_SMT: CLABCONF0: = SB-iMX8PLUS
P27 = HDR_2x5_100MIL_SMT: CLABCONF0: = SB-iMX8PLUS
Q4 = P-MOS,_1.5A,_8V: CLABCONF0: = SB-iMX8PLUS
R51 = 0R,_0402_1_22: CLABCONF0: = SB-iMX8PLUS
R71 = 10K,1%,0402,1_16W_3: CLABCONF0: = SB-iMX8PLUS
R78 = 0R,_0402_1_29: CLABCONF0: = SB-iMX8PLUS
R155 = 0R,_0402_1_25: CLABCONF0: DNP
R156 = 0R,_0402_1_11: CLABCONF0: = SB-iMX8PLUS
R157 = 0R,_0402_1_19: CLABCONF0: DNP
R158 = 0R,_0402_1_21: CLABCONF0: = SB-iMX8PLUS
R159 = 0R,_0402_1_16: CLABCONF0: DNP
R160 = 0R,_0402_1_3: CLABCONF0: = SB-iMX8PLUS
R161 = 0R,_0402_1_18: CLABCONF0: = SB-iMX8PLUS
R162 = 0R,_0402_1_12: CLABCONF0: DNP
R163 = 0R,_0402_1_30: CLABCONF0: = SB-iMX8PLUS
R164 = 0R,_0402_1_28: CLABCONF0: DNP
R166 = 0R,_0402_1_4: CLABCONF0: DNP
R167 = 0R,_0402_1_23: CLABCONF0: DNP
R168 = 0R,_0402_1_1: CLABCONF0: = SB-iMX8PLUS
R174 = 0R,_0402_1_24: CLABCONF0: = SB-iMX8PLUS
R177 = 0R,_0402_1_7: CLABCONF0: = SB-iMX8PLUS
R178 = 0R,_0402_1_6: CLABCONF0: = SB-iMX8PLUS
R179 = 0R,_0402_1_26: CLABCONF0: = SB-iMX8PLUS
R181 = 0R,_0402_1_14: CLABCONF0: = SB-iMX8PLUS
R189 = 4_0.75K,1%,0402,1_16W_1: CLABCONF0: = SB-iMX8PLUS
R190 = 4_0.75K,1%,0402,1_16W: CLABCONF0: = SB-iMX8PLUS
R192 = 0R,_0402_1_9: CLABCONF0: = SB-iMX8PLUS
R196 = 0R,_0402_1_27: CLABCONF0: = SB-iMX8PLUS
R197 = 0R,_0402_1_20: CLABCONF0: = SB-iMX8PLUS
R198 = 0R,_0402_1_17: CLABCONF0: = SB-iMX8PLUS
R199 = 0R,_0402_1_2: CLABCONF0: = SB-iMX8PLUS
R205 = 0R,_0402_0_1: CLABCONF0: DNP; P/N: 161C00005S
R228 = 0R,_0402_1_10: CLABCONF0: = SB-iMX8PLUS
R230 = 0R,_0402_1_13: CLABCONF0: = SB-iMX8PLUS
R231 = 0R,_0402_1_15: CLABCONF0: = SB-iMX8PLUS
R234 = 0R,_0402_0_2: CLABCONF0: DNP; P/N: 161C00005S
R235 = 10K,1%,0402,1_16W_0_2: CLABCONF0: = SB-iMX8PLUS
R325 = 10K,1%,0402,1_16W_0_3: CLABCONF0: = SB-iMX8PLUS
R330 = 10K,1%,0402,1_16W_0: CLABCONF0: DNP
R332 = 60.4R_1%,_0402_3: CLABCONF0: = SB-iMX8PLUS
R333 = 60.4R_1%,_0402: CLABCONF0: = SB-iMX8PLUS
R342 = 0R,_0402_1_8: CLABCONF0: DNP
R343 = 60.4R_1%,_0402_1: CLABCONF0: = SB-iMX8PLUS
R346 = 60.4R_1%,_0402_2: CLABCONF0: = SB-iMX8PLUS
R347 = 0R,_0402_1_5: CLABCONF0: DNP
RN17 = RN,10K,8P4R@0805: CLABCONF0: = SB-iMX8PLUS
U35 = PCA9555_1: CLABCONF0: = SB-iMX8PLUS
U58 U59 = ATA6563: CLABCONF0: = SB-iMX8PLUS; P/N: 116A00380S
C52 = 10uF,6.3V,0603,20%X5R: CLABCONF0: = SB-iMX8PLUS
C278 = 1uF,X5R,6.3V,0402: CLABCONF0: = SB-iMX8PLUS; P/N: 151D10510S
D7 = ZENER_24V_500mW_SOD-123: CLABCONF0: DNP
L8 = INC_DELTA_SI43-100,_10uH: CLABCONF0: = SB-iMX8PLUS; CLABCONF1: <null>
P22 = FPC_Connector_0: CLABCONF0: = SB-iMX8PLUS; P/N: 182P03002S
P45 = FPC_Connector_4: CLABCONF0: = SB-iMX8PLUS; P/N: 182P00802S
R36 = 2.2R,5%,0402,1_16W: CLABCONF0: = SB-iMX8PLUS; P/N: 161C00005S
R39 = 2.2R,5%,0402,1_16W_1: CLABCONF0: = SB-iMX8PLUS; P/N: 161C06R25S
R41 = 0R,_0402_5: CLABCONF0: = SB-iMX8PLUS
R75 = 2.2K,5%,0402.1_16W: CLABCONF0: = SB-iMX8PLUS
R138 = 0R,_0402_4: CLABCONF0: = SB-iMX8PLUS
R210 = 0R,_0402_1: CLABCONF0: = SB-iMX8PLUS
R239 = 0R,_0402: CLABCONF0: = SB-iMX8PLUS
U15 = AIC1647_0: CLABCONF0: = SB-iMX8PLUS; P/N: 123C40000S
U32 = IP4220CZ6_0: CLABCONF0: = SB-iMX8PLUS
U11 = 74LCX04_sgl_gate_TSSOP-14: CLABCONF0: = SB-iMX8PLUS

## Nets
1V8_PER: R72.1 ; also on sheet 10 11 13 15
3V3_EXP: C193.1 Q4.3(D) R157.1 U35.21(VDD)
3V3_PER: C30.1 C31.1 C32.1 C33.1 C34.1 C35.1 C36.1 C37.1 C177.2 C185.1 C186.1 C367.1 C373.1 C833.1 C887.1 C889.1 E14.1 P25.2 P45.3 Q4.2(S) R71.2 R78.2 R83.2 R138.1 R157.2 R159.2 R166.2 R167.2 R189.1 R190.1 R201.1 R210.1 R217.1 R235.1 R320.2 R897.1 R900.2 U10.3(DCVDD) U10.5(DBVDD) U10.12(HPVDD) U10.18(AVDD) U11.14(VCC) U32.5(VBUS) U41.9(VCC) U42.8(VCC33) U58.5(VIO) U59.5(VIO) ; also on sheet 8 9 10 11 12 13 14 15
5V0_PER: C368.2 C371.2 C777.2 C778.2 C779.2 C831.1 C886.1 C888.1 R128.2 R319.2 R888.1 R890.1 R891.1 R894.1 U34.6(Vin) U34.7(Vin) U42.30(VDD5) U43.6(Vin) U43.7(Vin) U58.3(VCC) U59.3(VCC) ; also on sheet 8 9 13
AGND: C29.1 C34.2 C35.2 C36.2 C37.2 C42.2 C43.2 C44.2 C45.2 J6.1(COM) J7.1(COM) J8.1(COM) R18.2 R19.2 R25.1 R26.1 R27.2 R99.2 R106.2 U10.15(HPGND) U10.19(AGND) U10.29(PAD) ; also on sheet 15
GND: C3.2 C4.2 C5.2 C6.2 C7.2 C8.2 C9.1 C30.2 C31.2 C32.2 C33.2 C46.1 C47.1 C50.2 C51.2 C52.2 C53.2 C54.1 C60.2 C61.2 C63.2 C66.2 C69.2 C70.2 C127.2 C177.1 C185.2 C186.2 C187.1 C188.2 C192.1 C193.2 C194.2 C195.1 C278.2 C367.2 C368.1 C371.1 C373.2 C733.2 C760.2 C761.2 C774.1 C775.1 C777.1 C778.1 C779.1 C831.2 C832.1 C833.2 C886.2 C887.2 C888.2 C889.2 C913.1 C916.1 C917.1 C918.2 C919.2 C920.2 C921.2 C922.2 C923.2 C924.2 J3.4(GND) J3.7(GND) J3.SH1 J3.SH2 J5.A1(GND0) J5.A12(GND1) J5.B1(GND2) J5.B12(GND3) J5.Sh1 J5.Sh2 J5.Sh3 J5.Sh4 L17.5(GND) L17.6(GND) L18.5(GND) L18.6(GND) L19.5(GND) L19.6(GND) L20.5(GND) L20.6(GND) L21.5(GND) L21.6(GND) L22.5(GND) L22.6(GND) L23.5(GND) L23.6(GND) L24.5(GND) L24.6(GND) L59.5(GND) L59.6(GND) L60.5(GND) L60.6(GND) L61.5(GND) L61.6(GND) L62.5(GND) L62.6(GND) L63.5(GND) L63.6(GND) P1.1 P1.19 P1.37 P1.55 P1.71 P1.87 P1.105 P1.123 P1.141 P1.159 P1.177 P1.195 P4.3 P6.S1(SHIELD) P6.S2(SHIELD) P7.4 P7.6 P22.6 P22.9 P22.12 P22.15 P22.18 P22.21 P22.22 P22.24 P22.29 P22.30 P22.NC1 P22.NC2 P25.33 P26.S1(SHIELD) P26.S2(SHIELD) P45.1 P45.8 P45.NC1 P45.NC2 Q1.1(S) Q1.4(S) Q14.1(S) R34.1 R35.2 R36.2 R46.2 R47.2 R48.2 R49.2 R51.1 R75.2 R76.2 R99.1 R106.1 R172.2 R207.2 R208.2 R220.2 R243.1 R252.1 R321.1 R323.2 R324.2 R325.1 R892.1 R893.1 RN17.2(RB1) RN17.3(RC1) RN17.4(RD1) U10.4(DGND) U10.25(MODE) U10.26(CSB) U11.7(GND) U15.2(GND) U32.2(GND) U34.4(GND) U35.9(VSS) U35.25(CPAD) U41.4(GND) U42.13(GND) U42.28(GND) U42.29(EN_CC#) U42.Tpad(TPAD) U43.4(GND) U58.2(GND) U59.2(GND) X1.2 X1.4 ; also on sheet 8 9 10 11 12 13 14 15
VCC_RTC: C3.1 P1.183 ; also on sheet 13
A_IN: C48.2 R32.2
ADCLRC: R23.1 R24.1 U10.11(ADCLRC)
ALT_BOOT: P1.185 R216.1
AMP_IN: R31.2 R32.1 U11.3(I)
AMP_OUT: R31.1 U11.1(I) U11.4(12)
AMP_SPDIF_RX: E2.1 R139.2 U11.2(12)
AMPR: C28.2 R17.1
AUD_VMID: C44.1 C45.1 U10.20(VMID)
AUDIO_IN_DIG: C48.1 J7.2(AUX) R34.2
AUDIO_OUT_DIG: C50.1 J8.2(AUX) R33.2 R35.1
BOOT_MODE1: P27.3
BOOT_MODE2: P27.5
BOOT_MODE3: P27.7
CAN1_CAP: C760.1 R332.1 R333.2
CAN1_H: P4.1 R332.2 U58.7(CANH)
CAN1_L: P4.2 R333.1 U58.6(CANL)
CAN1_RX/SAI2_TXC: P1.63 U58.4(RXD)
CAN1_STBY: R321.2 R342.2 U58.8(STBY)
CAN1_TX/SAI2_RXC: P1.65 U58.1(TXD)
CAN2_CAP: C761.1 R343.1 R346.2
CAN2_H: P4.4 R343.2 U59.7(CANH)
CAN2_L: P4.5 R346.1 U59.6(CANL)
CAN2_RX/SAI2_MCLK: P1.192 U59.4(RXD)
CAN2_STBY: R325.2 R347.2 U59.8(STBY)
CAN2_TX/SAI2_TXD0: P1.194 U59.1(TXD)
CARRIER_3V3_GPIO0_0: R156.2 U35.1(I/O0.0)
CARRIER_3V3_GPIO0_1: R168.2 U35.2(I/O0.1)
CARRIER_3V3_GPIO0_2: R158.2 U35.3(I/O0.2)
CARRIER_3V3_GPIO0_3: R174.2 U35.4(I/O0.3)
CARRIER_3V3_GPIO0_4: R196.2 U35.5(I/O0.4)
CARRIER_3V3_GPIO0_5: R197.2 U35.6(I/O0.5)
CARRIER_3V3_GPIO0_6: R177.2 U35.7(I/O0.6)
CARRIER_3V3_GPIO0_7: R199.2 U35.8(I/O0.7)
CARRIER_3V3_GPIO1_0: R178.2 U35.10(I/O1.0)
CARRIER_3V3_GPIO1_1: R179.2 U35.11(I/O1.1)
CARRIER_3V3_GPIO1_2: R181.2 U35.12(I/O1.2)
CARRIER_3V3_GPIO1_3: R198.2 U35.13(I/O1.3)
CARRIER_3V3_GPIO1_4: R192.2 U35.14(I/O1.4)
CARRIER_3V3_GPIO1_5: R228.2 U35.15(I/O1.5)
CARRIER_3V3_GPIO1_6: R230.2 U35.16(I/O1.6)
CARRIER_3V3_GPIO1_7: R231.2 U35.17(I/O1.7)
CDC_BCLK: R20.2 U10.7(BCLK)
CODEC_XTALIN: C46.2 R28.1 U10.1(XTI/MCLK) X1.1(Y1)
CODEC_XTALOUT: C47.2 U10.2(XTO) X1.3(Y3)
CSI1_B_FLASH_OUT: R181.1 ; also on sheet 10
CSI1_B_RST: R179.1 ; also on sheet 10
CSI1_B_TRG: R198.1 ; also on sheet 10
CSI1_CKN: P1.184 ; also on sheet 10
CSI1_CKP: P1.182 ; also on sheet 10
CSI1_DN0: P1.23 ; also on sheet 10
CSI1_DN1: P1.29 ; also on sheet 10
CSI1_DN2: P1.17 ; also on sheet 10
CSI1_DN3: P1.9 ; also on sheet 10
CSI1_DP0: P1.21 ; also on sheet 10
CSI1_DP1: P1.27 ; also on sheet 10
CSI1_DP2: P1.15 ; also on sheet 10
CSI1_DP3: P1.7 ; also on sheet 10
CSI1_PWR_DWN_B: R178.1 ; also on sheet 10
CSI2_B_FLASH_OUT: R231.1 ; also on sheet 11
CSI2_B_RST: R228.1 ; also on sheet 11
CSI2_B_TRG: R230.1 ; also on sheet 11
CSI2_CKN: P1.83 ; also on sheet 11
CSI2_CKP: P1.85 ; also on sheet 11
CSI2_DN0: P1.89 ; also on sheet 11
CSI2_DN1: P1.107 ; also on sheet 11
CSI2_DN2: P1.113 ; also on sheet 11
CSI2_DN3: P1.119 ; also on sheet 11
CSI2_DP0: P1.91 ; also on sheet 11
CSI2_DP1: P1.109 ; also on sheet 11
CSI2_DP2: P1.115 ; also on sheet 11
CSI2_DP3: P1.121 ; also on sheet 11
CSI2_PWR_DWN_B: R192.1 ; also on sheet 11
DRP_ADDR: R890.2 R892.2 U42.22(ADDR)
DRP_CMODE: R888.2 U42.3(CURRENT_MODE)
DRP_DIR: R897.2 U42.11(DIR)
DRP_ENMUX_N: R893.2 U42.12(EN_MUX#)
DRP_ID: R887.2 R896.1 R898.1 U42.27(ID)
DRP_RXN1: L22.2 U42.14(RX1N)
DRP_RXN2: L20.1 U42.18(RX2N)
DRP_RXP1: L22.1 U42.15(RX1P)
DRP_RXP2: L20.2 U42.19(RX2P)
DRP_TXN1: C339.2 U42.16(TX1N)
DRP_TXN2: C354.2 U42.20(TX2N)
DRP_TXP1: C338.2 U42.17(TX1P)
DRP_TXP2: C351.2 U42.21(TX2P)
DRP_VBUS_DET: R236.1 R237.2 U42.5(VBUS_DET)
DRP_VCFAULT_N: R891.2 R899.2 U42.24(VCONN_FAULT_N)
DSI1_CN: L61.2 P22.13
DSI1_CP: L61.1 P22.14
DSI1_N0: L59.2 P22.7
DSI1_N1: L60.2 P22.10
DSI1_N2: L62.2 P22.16
DSI1_N3: L63.2 P22.19
DSI1_P0: L59.1 P22.8
DSI1_P1: L60.1 P22.11
DSI1_P2: L62.1 P22.17
DSI1_P3: L63.1 P22.20
DSI_BCKLIGHT_FB: D7.2(ANODE) R41.2 U15.3(FB)
DSI_BCKLIGHT_IN: C51.1 C52.1 L8.1 R210.2 R229.1 U15.6(IN)
DSI_DISP_IOVCC: C54.2 C188.1 P22.27 R83.1
DSI_DISP_RESET: P22.26 R75.1 R196.1
DSI_DISP_VCI: C53.1 C187.2 P22.28 R138.2
DSI_LED_A: C278.1 D2.CATHODE D7.1(CATHODE) P22.4 U15.5(OVP)
DSI_LED_EN: R211.2 R229.2 U15.4(EN/PWM)
DSI_LED_K: P22.2 R39.1 R41.1
DSI_TOUCH_RESET: P45.7 R197.1 U32.1(IO1)
DSI_WLD_RES: R36.1 R39.2
DSI_WLD_SW: D2.ANODE L8.2 U15.1(LX)
EARC_N_HPD: P1.129 ; also on sheet 9
EARC_P_UTIL: P1.135 ; also on sheet 9
ECSPI2_MISO: P1.152 P25.29
ECSPI2_MOSI: P1.148 P25.27
ECSPI2_SCLK: P1.154 P25.31
ECSPI2_SS0: P1.146 P25.25
ENET1_TD2_CM: P1.62 P27.10
ENET2_TD2_CM: P1.128 P25.15
ENET_MDC_CM: P1.52 P25.7
ENET_MDIO_CM: P1.97 P25.5
ETH0_CT1A: C60.1 C61.1 P6.P5(CT)
ETH0_CT1B: C63.1 C70.1 P26.P5(CT)
ETH1_CT2A: C66.1 P6.P6(CT)
ETH1_CT2B: C69.1 P26.P6(CT)
ETH1_GREEN_LED_CAT: P6.P11(LED1_C) R46.1
ETH1_LED_ACT/PHY1ADDRESS2: P1.4 P6.P12(LED1_A)
ETH1_LINK-LED_10_100: D1.1(ANODE1) P1.22
ETH1_LINK-LED_1000/INTSELECT: D1.2(ANODE2) P1.16
ETH1_MDI0N: P1.6 P6.P2(MDI0-)
ETH1_MDI0P: P1.8 P6.P1(MDI0+)
ETH1_MDI1N: P1.12 P6.P4(MDI1-)
ETH1_MDI1P: P1.14 P6.P3(MDI1+)
ETH1_MDI2N: P1.18 P6.P8(MDI2-)
ETH1_MDI2P: P1.20 P6.P7(MDI2+)
ETH1_MDI3N: P1.24 P6.P10(MDI3-)
ETH1_MDI3P: P1.26 P6.P9(MDI3+)
ETH1_YELLOW_LED_AN: D1.3(CATHODE) P6.P14(LED2_A)
ETH1_YELLOW_LED_CAT: P6.P13(LED2_C) R47.1
ETH2_GREEN_LED_CAT: P26.P11(LED1_C) R48.1
ETH2_LED_ACT/PHY1ADDRESS2: P1.25 P26.P12(LED1_A)
ETH2_LINK-LED_10_100: D12.1(ANODE1) P1.34
ETH2_LINK-LED_1000/INTSELECT: D12.2(ANODE2) P1.40
ETH2_MDI0N: P1.30 P26.P2(MDI0-)
ETH2_MDI0P: P1.32 P26.P1(MDI0+)
ETH2_MDI1N: P1.36 P26.P4(MDI1-)
ETH2_MDI1P: P1.38 P26.P3(MDI1+)
ETH2_MDI2N: P1.42 P26.P8(MDI2-)
ETH2_MDI2P: P1.44 P26.P7(MDI2+)
ETH2_MDI3N: P1.48 P26.P10(MDI3-)
ETH2_MDI3P: P1.50 P26.P9(MDI3+)
ETH2_YELLOW_LED_AN: D12.3(CATHODE) P26.P14(LED2_A)
ETH2_YELLOW_LED_CAT: P26.P13(LED2_C) R49.1
EXP_nPWREN: Q14.2(G) R76.1 R161.2
EXP_nPWREN_G: Q4.1(G) R71.1 R160.1
EXPANDER_A0: R166.1 RN17.5(RD2) U35.18(A0)
EXPANDER_A1: R167.1 RN17.6(RC2) U35.23(A1)
EXPANDER_A2: R159.1 RN17.7(RB2) U35.24(A2)
GPIO_PHY1_INT: P1.134 P25.19
GPIO_PHY1_WOL: P1.2 P25.8
GPIO_PHY2_INT: P1.136 P25.21
GPIO_PHY2_WOL: P1.140 P25.23
HASW_EN: Q1.6(D) R320.1 U43.5(EN)
HASW_IP: R324.1 U43.8(IP)
HDMI_CEC: P1.153 ; also on sheet 9
HDMI_DDC_SCL: P1.147 ; also on sheet 9
HDMI_DDC_SDA: P1.149 ; also on sheet 9
HDMI_HPD: P1.151 ; also on sheet 9
HDMI_TXCN: P1.155 ; also on sheet 9
HDMI_TXCP: P1.157 ; also on sheet 9
HDMI_TXN0: P1.137 ; also on sheet 9
HDMI_TXN1: P1.143 ; also on sheet 9
HDMI_TXN2: P1.161 ; also on sheet 9
HDMI_TXP0: P1.139 ; also on sheet 9
HDMI_TXP1: P1.145 ; also on sheet 9
HDMI_TXP2: P1.163 ; also on sheet 9
HOSTA_USB_DN: J3.2(DN) L21.4
HOSTA_USB_DP: J3.3(DP) L21.3
HUB_OE: R243.2 U41.8(\\~{O}E)
I2C3_SCL: P1.167 P25.32 R202.2
I2C3_SCL_CM: P45.4 R190.2 R202.1 R205.1 U10.28(SCLK) U32.6(IO4) U35.19(SCL) U42.26(SCL) ; also on sheet 8 10 12 14
I2C3_SDA: P1.169 P25.34 R203.2
I2C3_SDA_CM: P45.5 R189.2 R203.1 R204.1 U10.27(SDIN) U32.4(IO3) U35.20(SDA) U42.25(SDA) ; also on sheet 8 10 12 14
I2C4_SCL: P1.173 P25.9 ; also on sheet 11 12
I2C4_SDA: P1.175 P25.11 ; also on sheet 11
INT_EXP: R234.1 R235.2 U35.22(\\~{IN}T)
INT_ID_PWR: C832.2 R887.1 R889.1 R894.2 R900.1
J_MOD_8: P7.8 R155.2
JTACRST_OD: D10.ANODE R162.2 R163.1 R164.1
JTAG_HDR_10: P7.10 R51.2
JTAG_MOD: P1.108 R155.1
JTAG_POWER: C192.2 D14.ANODE P7.2 R69.1 R70.1 R72.2 R78.1
JTAG_RST: D10.CATHODE P7.9 R162.1 R330.2
JTAG_RST_PU: D14.CATHODE R330.1
JTAG_TCK: P1.122 P7.3
JTAG_TDI: P1.120 P7.7 R70.2
JTAG_TDO: P1.126 P7.5
JTAG_TMS: P1.124 P7.1 R69.2
LHPOUT: C41.1 J8.4(L) R19.1
LHPOUT_T: C41.2 U10.13(LHPOUT)
LIN_T: C39.2 C42.1 R22.1 R25.2
LLINEIN: J7.4(L) R22.2
LLINEIN_T: C39.1 U10.24(LLINEIN)
LVDS0_CLK_N: P1.104 ; also on sheet 8
LVDS0_CLK_P: P1.106 ; also on sheet 8
LVDS0_TX0_N: P1.110 ; also on sheet 8
LVDS0_TX0_P: P1.112 ; also on sheet 8
LVDS0_TX1_N: P1.92 ; also on sheet 8
LVDS0_TX1_P: P1.94 ; also on sheet 8
LVDS0_TX2_N: P1.98 ; also on sheet 8
LVDS0_TX2_P: P1.100 ; also on sheet 8
LVDS0_TX3_N: P1.116 ; also on sheet 8
LVDS0_TX3_P: P1.118 ; also on sheet 8
LVDS_DISP_RESET: R177.1 ; also on sheet 8
LVDS_DSI_CKN: L61.3 P1.35
LVDS_DSI_CKP: L61.4 P1.33
LVDS_DSI_DN0: L59.3 P1.41
LVDS_DSI_DN1: L60.3 P1.47
LVDS_DSI_DN2: L62.3 P1.53
LVDS_DSI_DN3: L63.3 P1.59
LVDS_DSI_DP0: L59.4 P1.39
LVDS_DSI_DP1: L60.4 P1.45
LVDS_DSI_DP2: L62.4 P1.51
LVDS_DSI_DP3: L63.4 P1.57
LVDS_LED_EN: E2.3 R147.1 ; also on sheet 8
LVDS_TOUCH_RESET: R199.1 ; also on sheet 8
MIC_IN: C28.1 C29.2 J6.4(L) R16.2 R18.1
MICBIAS: R16.1 U10.21(MICBIAS)
MICIN: R17.2 U10.22(MICIN)
MIPI_FPC_INT: P45.6 R239.2 U32.3(IO2)
mPCIe_PERST: R156.1 ; also on sheet 12
mux_PCIe_USB_DN: U41.6(HSD2-) ; also on sheet 12
mux_PCIe_USB_DP: U41.2(HSD2+) ; also on sheet 12
MUX_USB3_SEL: E14.2 Q1.2(G) R172.1 U41.10(SEL)
MUX_USB_DN: L21.1 U41.7(HSD1-)
MUX_USB_DP: L21.2 U41.1(HSD1+)
PB_ALT_BOOT: E21.1 R216.2 SW7.2 SW7.4
PB_RESET: R215.2 R218.2 SW6.2 SW6.4
PCIE_CLKN: P1.101 ; also on sheet 12
PCIE_CLKP: P1.103 ; also on sheet 12
PCIE_RXN: P1.133 ; also on sheet 12
PCIE_RXP: P1.131 ; also on sheet 12
PCIE_TXN: P1.127 ; also on sheet 12
PCIE_TXP: P1.125 ; also on sheet 12
PHY_2V5: C8.1 P1.102
PIMICPOWER_ON: E10.2 R220.1
PMIC_ON_REQ: P1.202 ; also on sheet 13
PMIC_STBY_REQ: P1.181 ; also on sheet 13
POR_B_3P3: E10.1 P1.171 R163.2 R215.1 R219.1 ; also on sheet 12
PWRBTN: P1.165 R223.1
Q1_5: Q1.5(G) R252.2 R898.2
Q14_6: Q14.6(D) R160.2
RGMII_VIO2: P1.138 P27.1
RHPOUT: C40.1 J8.3(R) R27.1
RHPOUT_T: C40.2 U10.14(RHPOUT)
RIN_T: C38.2 C43.1 R21.1 R26.2
RLINEIN: J7.3(R) R21.2
RLINEIN_T: C38.1 U10.23(RLINEIN)
RSVD/BOOT_MODE1: P1.144
RSVD/BOOT_MODE2: P1.156
RSVD/BOOT_MODE3: P1.162
RSVD/SER_BOOT_ENH: E22.1 P1.203
RSVD/SYS_I2C_SCL: P1.3 P25.6 R205.2
RSVD/SYS_I2C_SDA: P1.5 P25.4 R204.2
RSVD/SYS_RST_PMIC: P1.142 R164.2 R218.1
SAI3_MCLK: P1.187 R28.2
SAI3_RXC/UART2_CTS: P1.199 P25.13
SAI3_RXD/UART2_RTS: P1.201 U10.10(ADCDAT)
SAI3_RXFS: P1.197 R24.2
SAI3_TXC: P1.191 R20.1
SAI3_TXD: P1.193 U10.8(DACDAT)
SAI3_TXFS: P1.189 R23.2 U10.9(DACLRC)
SD1_CLK: P1.54 P25.10
SD1_CMD: P1.56 P25.12
SD1_DATA0: P1.58 P25.14
SD1_DATA1: P1.60 P25.16
SD1_DATA2: P1.69 P25.30
SD1_DATA3: P1.66 P25.18
SD1_DATA4: P1.68 P25.20 R342.1
SD1_DATA5: P1.70 P25.22 R347.1 ; also on sheet 12
SD1_DATA6: P1.72 P25.24 R239.1
SD1_DATA7: P1.76 P25.28 ; also on sheet 12
SD1_RESET_B: P1.130 P25.17 R234.2 R901.2
SD1_STROBE: P1.74 P25.26 R161.1
SD2_CLK: P1.80 ; also on sheet 14
SD2_CMD: P1.82 ; also on sheet 14
SD2_DATA0: P1.84 ; also on sheet 14
SD2_DATA1: P1.86 ; also on sheet 14
SD2_DATA2: P1.88 ; also on sheet 14
SD2_DATA3: P1.90 ; also on sheet 14
SD2_nCD: P1.61 ; also on sheet 14
SD2_RESET_B: P1.179 P27.9
SD2_WP: P1.67 ; also on sheet 8
SER_BOOT: E22.2 R217.2
SPDIF_EXT_CLK: P1.49 R211.1
SPDIF_OUT1C: C49.1 R33.1
SPDIF_RX: E2.2 P1.43 R139.1 R147.2
SPDIF_TX: C49.2 P1.31
SW_ALT_BOOT: E21.2 R201.2 SW7.1 SW7.3
SW_PWRBTN: R208.1 SW5.1 SW5.3
SW_RES: R207.1 SW6.1 SW6.3
SWPWRBTN: R219.2 R223.2 SW5.2 SW5.4
TCCAP_SSTXN1: C339.1 L19.2
TCCAP_SSTXN2: C354.1 L24.1
TCCAP_SSTXP1: C338.1 L19.1
TCCAP_SSTXP2: C351.1 L24.2
TCSW_EN: Q1.3(D) R319.1 R899.1 U34.5(EN)
TCSW_FLG#: R128.1 U34.1(FLG)
TCSW_IP: R323.1 U34.8(IP)
TYPEC_CC1: J5.A5(CC1) U42.2(CC1)
TYPEC_CC2: J5.B5(CC2) U42.1(CC2)
TYPEC_DN: J5.A7(DN1) J5.B7(DN2) L23.3
TYPEC_DP: J5.A6(DP1) J5.B6(DP2) L23.4
TYPEC_SSRXN1: J5.B10(SSRXN1) L22.3
TYPEC_SSRXN2: J5.A10(SSRXN2) L20.4
TYPEC_SSRXP1: J5.B11(SSRXP1) L22.4
TYPEC_SSRXP2: J5.A11(SSRXP2) L20.3
TYPEC_SSTXN1: J5.A3(SSTXN1) L19.3
TYPEC_SSTXN2: J5.B3(SSTXN2) L24.4
TYPEC_SSTXP1: J5.A2(SSTXP1) L19.4
TYPEC_SSTXP2: J5.B2(SSTXP2) L24.3
UART1_CTS: P1.77 P25.1
UART1_RTS: P1.79 P25.3
UART1_RXD: P1.73 ; also on sheet 14
UART1_TXD: P1.75 ; also on sheet 14
UART2_RXD: P1.117 ; also on sheet 14
UART2_TXD: P1.111 ; also on sheet 14
UART3_CTS: P1.99 P27.4
UART3_RTS: P1.81 P27.2
UART3_RXD: P1.93 P27.6
UART3_TXD: P1.95 P27.8
UART4_RXD: P1.11 ; also on sheet 14
UART4_TXD: P1.13 ; also on sheet 14
UART_DEBUGSEL: R158.1 ; also on sheet 14
USB1_DN: L23.2 P1.178
USB1_DP: L23.1 P1.176
USB1_ID: P1.174 R896.2
USB1_RXN: P1.188 U42.10(RXN)
USB1_RXP: P1.190 U42.9(RXP)
USB1_TCPC_nINT: R889.2 R901.1 U42.23(INT_N)
USB1_TXN: P1.198 U42.7(TXN)
USB1_TXP: P1.200 U42.6(TXP)
USB1_VBUS: C733.1 C774.2 C775.2 J5.A4(VBUS1) J5.A9(VBUS2) J5.B4(VBUS3) J5.B9(VBUS4) P1.180 R236.2 R237.1 U34.2(Vout) U34.3(Vout)
USB2_DN: P1.170 U41.5(D-)
USB2_DP: P1.172 U41.3(D+)
USB2_RXN: L17.2 P1.164
USB2_RXP: L17.1 P1.166
USB2_TX_N: C225.2 L18.2
USB2_TX_P: C224.2 L18.1
USB2_TXN: C225.1 P1.158
USB2_TXP: C224.1 P1.160
USB2_VBUS: P1.196 R895.2
USB3_HOSTA_SSRXN: J3.5(SSRXN) L17.3
USB3_HOSTA_SSRXP: J3.6(SSRXP) L17.4
USB3_HOSTA_SSTXN: J3.8(SSTXN) L18.3
USB3_HOSTA_SSTXP: J3.9(SSTXP) L18.4
USB3_HOSTA_VBUS: C127.1 J3.1(VBUS) R895.1 U43.2(Vout) U43.3(Vout)
V_SOM: C4.1 C5.1 C6.1 C7.1 C9.2 C194.1 C195.2 C913.2 C916.2 C917.2 C918.1 C919.1 C920.1 C921.1 C922.1 C923.1 C924.1 P1.10 P1.28 P1.46 P1.64 P1.78 P1.96 P1.114 P1.132 P1.150 P1.168 P1.186 P1.204 ; also on sheet 13 15

Not connected (* = marked no-connect by the designer): J5 A8(SBU1)* B8(SBU2)*; J6 2(AUX)* 3(R)* CN* CO*; J7 CN* CO*; J8 CN* CO*; P22 1* 3* 5* 23* 25*; P45 2*; R168 1*; R174 1*; RN17 1(RA1)* 8(RA2)*; U10 6(CLKOUT)* 16(LOUT)* 17(ROUT)*; U42 4(PORT)*; U43 1(FLG)*

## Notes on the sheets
sheet 1
- SB-iMX8PLUS
- BOARD REVISION: 1.0
- Page
- Description
- 01
- Block Diagram
- 02
- Carrier-board interface
- 03
- RJ-45 Ethernet connectors
- 04
- USB3.0, Type-C, Host
- 05
- Audio Codec
- 06
- JTAG, CAN, GPIO Exp., Misc.
- 07
- MIPI-DSI LCD
- 08
- LVDS LCD
- 09
- HDMI connector with eARC
- 10
- MIPI-CSI1 Connectors
- 11
- MIPI-CSI2 Connectors
- 12
- PCIe
- 13
- Power
- 14
- UART, RS232, SD, EEPROM
- 15
- Mechanical
sheet 2
- Carrier Board Interface
- M7 Debug
- DNP
- PWRON
- RESET
- DNP
- BT
- ALT.BOOT
- SER.BOOT EN
- DNP
- C3 is DNP,according to RTC's app. note
sheet 3
- Ethernet connector 1
- 100 Ohm
- 100 Ohm
- 100 Ohm
- 100 Ohm
- Ethernet connector 2
- 100 Ohm
- 100 Ohm
- 100 Ohm
- 100 Ohm
sheet 4
- USB3.0 Type-C
- USB1-C
- USB1_VBUS is isolated by 30K resistor on UCM
- DNP
- GPIO2_IO10
- # 90-Ohm diff pairs
- DNP
- Assembly ACAP to L26
- # 90-Ohm diff pairs
- CURRENT_MODE -The
  pin has 250 K internal pull-down.
  900 mA - Low (Default)
  1.5 A - 500K PU to VDD5
  3.0 A - 10K PU to VDD5
- Pin 27 (ADDR):
  PU - I2C 7-bit address is 0x67.
  PD - I2C 7-bit address is 0x47.
- 1.05A LIMIT
- # 90-Ohm diff pairs
- USB3.0 HOST with MUX to PCIe con.
- USB2_VBUS is isolated by 30K resistor on UCM
- USB2
- # 90-Ohm diff pairs
- In the  SOM-iMX8PLUS rev1.1,
  C225/C224 will be replaced with 0Ohm resistors
- # 90-Ohm differential pairs
- 1.05A LIMIT
sheet 5
- Audio Codec
- POWER CONSUMPTION:
  DBVDD = 1.5mA @ 3.3V (typ)
  DCVDD = 3.2mA @ 1.5V (typ) ==> assuming same current @ 3.3V
  HPVDD = 1.7mA @ 3.3V (typ)
  AVDD = 13.1mA @ 3.3V (typ)
  1.5+3.2+1.7+13.1=19.5mA @ 3.3V (typ):
  Assuming worst case is 50mA @ 3.3V
- Mic IN
- Place C93 and C94
  ACAP to U10 pins 5 and 4
- Place C97 and C98
  ACAP to U10 pins 3 and 4
- Place C99 and C100
  ACAP to U10 pins 18 and 19
- Place C95 and C170
  ACAP to U10 pins 12 and 15
- I2C ADDRESS: 0b0011010 (0x1AH)
- Audio IN
- CP
- DNP
- CP
- Audio OUT
- Keep analog signals clear from other signals at least 30mills
  Analog signals list will be provided in separate doc
- DNP
- DNP
- Keep S1 close to U11
  S1 width at least 20 mil
- DNP
- 20mil
- 20mil
- DNP
- SPDIF
- DNP
- DNP
sheet 6
- JTAG
- MISC connectors
- NXP refdes layout
- DNP
- TMS
- VCC
- TCK
- GND
- TDO
- GND
- TDI
- I2C to GPIO expander
- DNP
- DNP
- I2C Address:
  0x20
- Power of GPIO expander
- I2C connection provision
- DNP
- DNP
- CAN Buses
- GPIO2 [6]
- DNP
- Align with P4 Pin layout physical dimention
- GPIO2 [7]
- DNP
sheet 7
- MIPI-DSI LCD connector
- MIPI-DSI LCD back-light power
- Typical LED configuration: Two parallel chains of 6 serially connected LEDs
- # 100-Ohm diff pairs
- 19.2V/40mA
- DNP
- # 100-Ohm diff pairs
- MIPI-DSI touch-panel connector
- GPIO2 [8]
- Pinout of J5 reversed
   to FPC
